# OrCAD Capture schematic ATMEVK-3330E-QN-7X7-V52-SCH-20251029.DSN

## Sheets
1 01. TITLE: title: ATM3330E EVALUATION BOARD; rev: 5.2; note: 052-50-611-xxxx
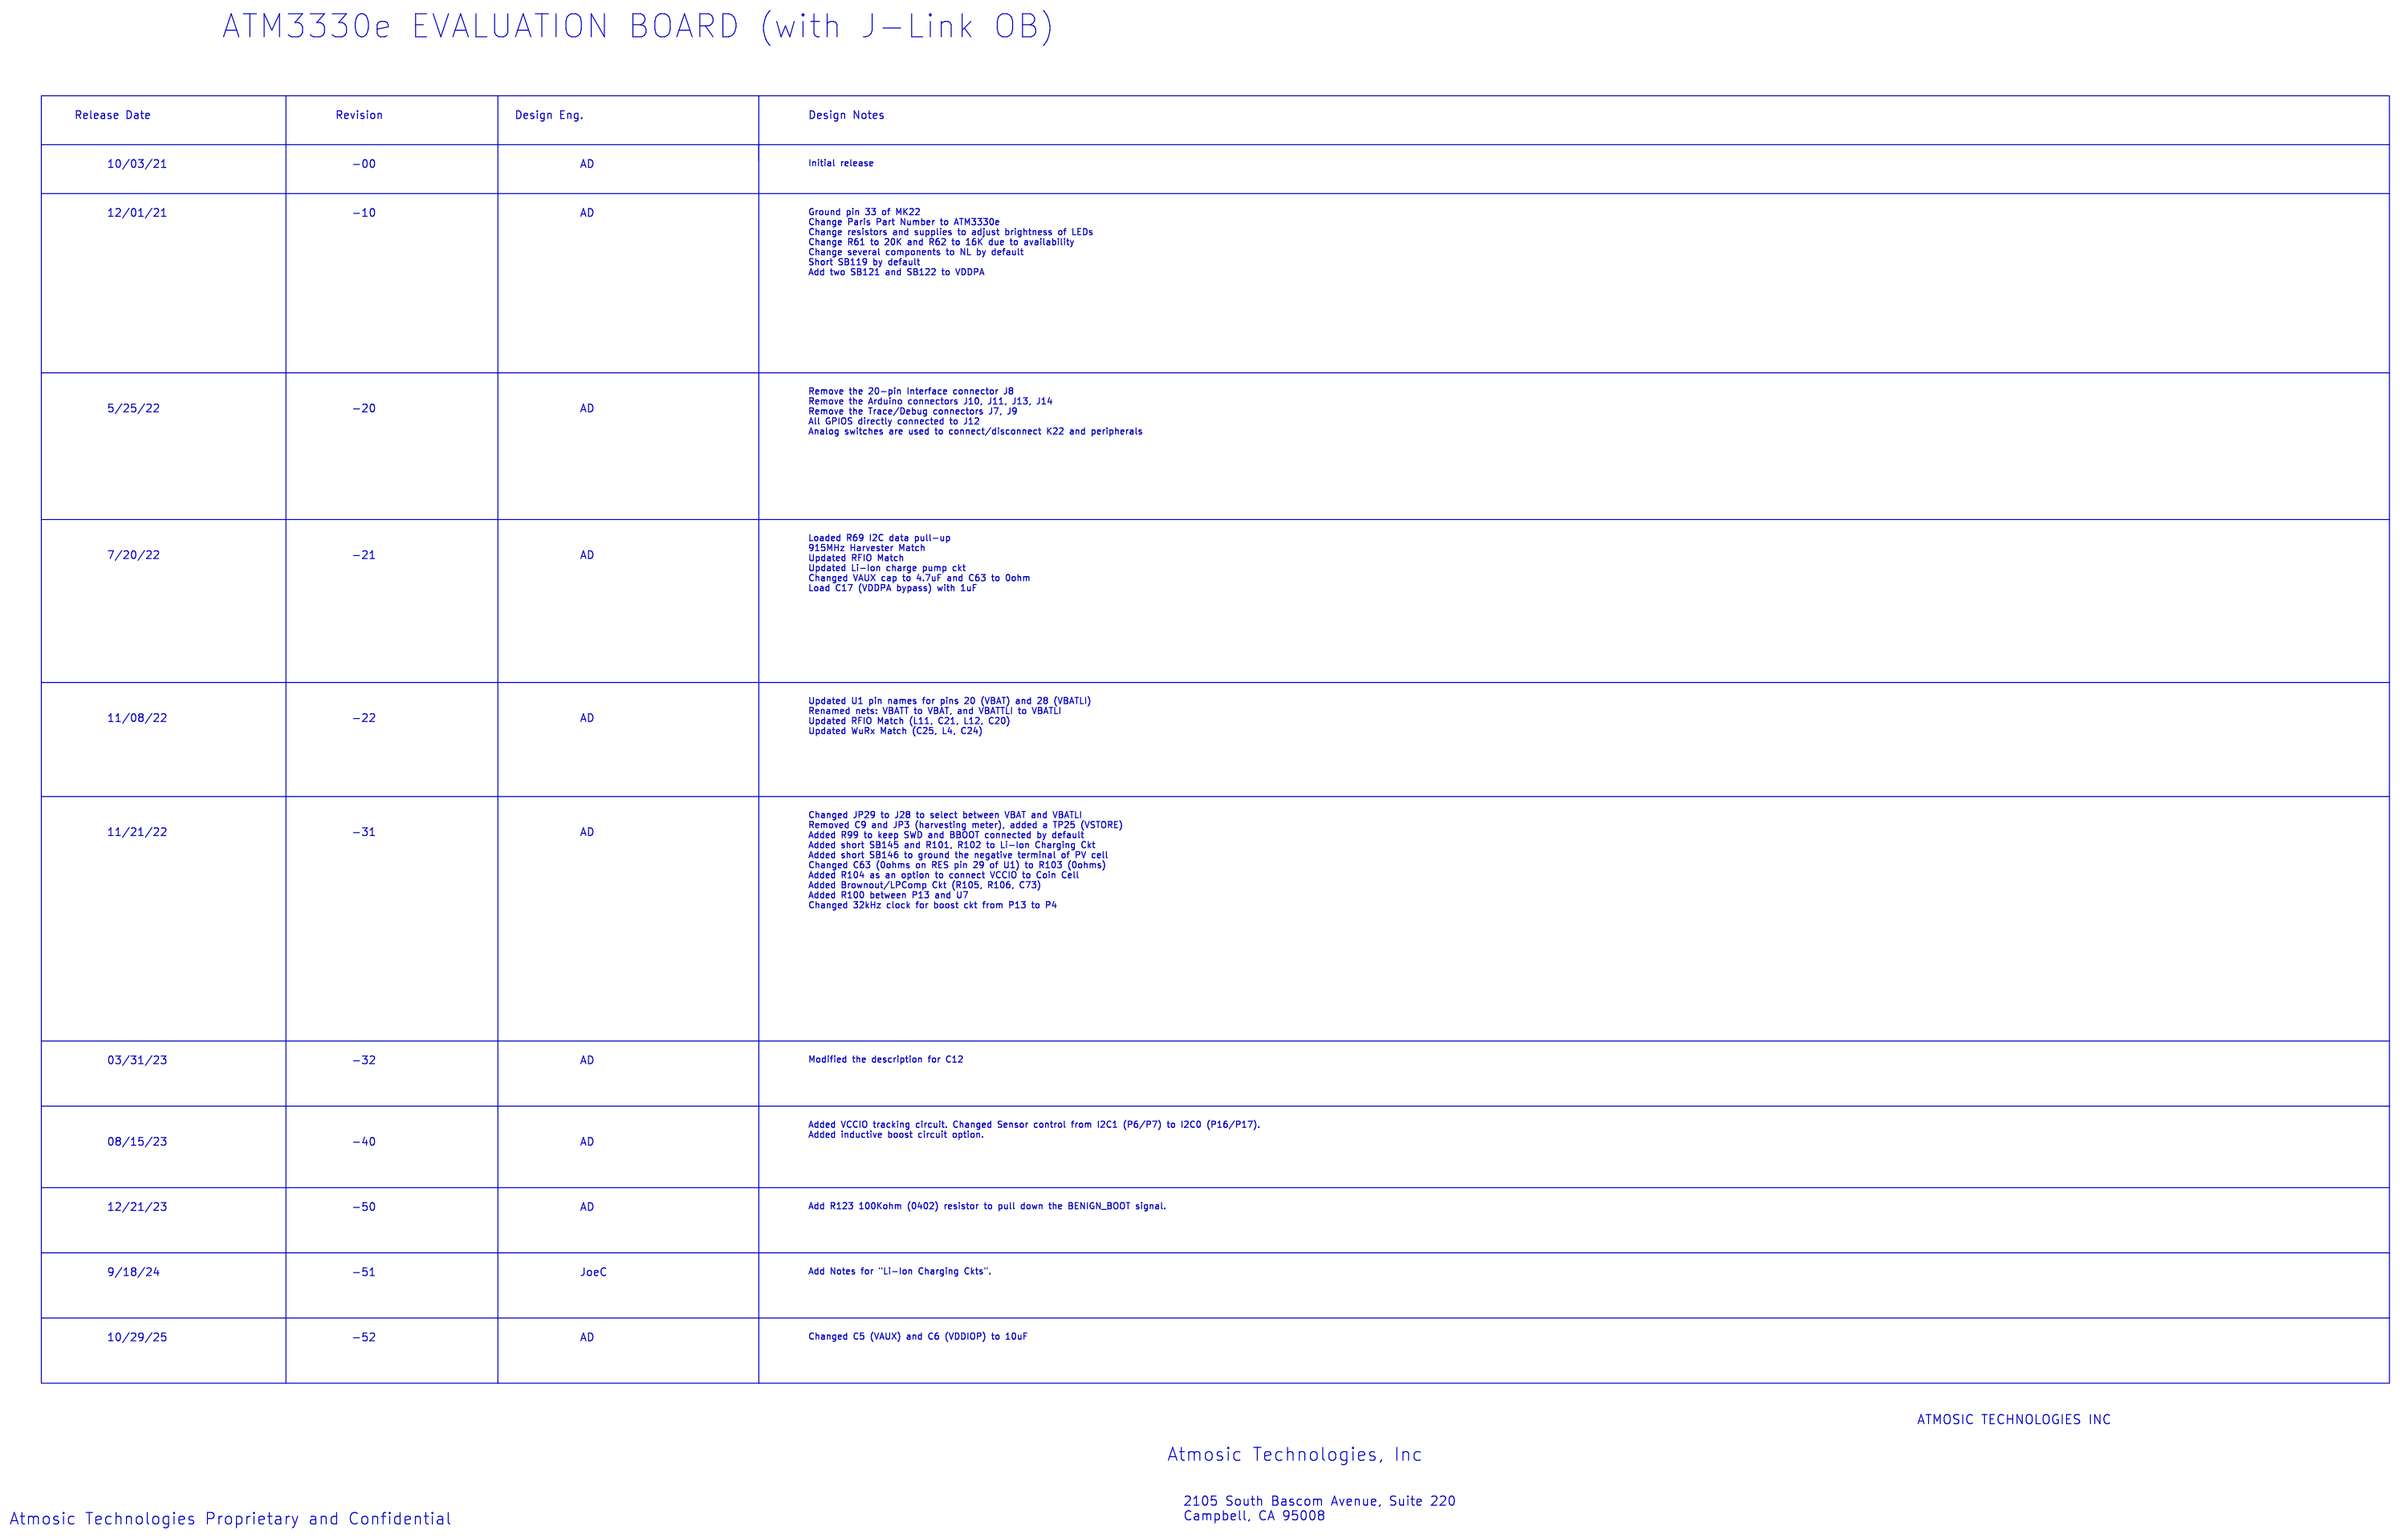
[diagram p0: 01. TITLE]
2 02. Block Diagram
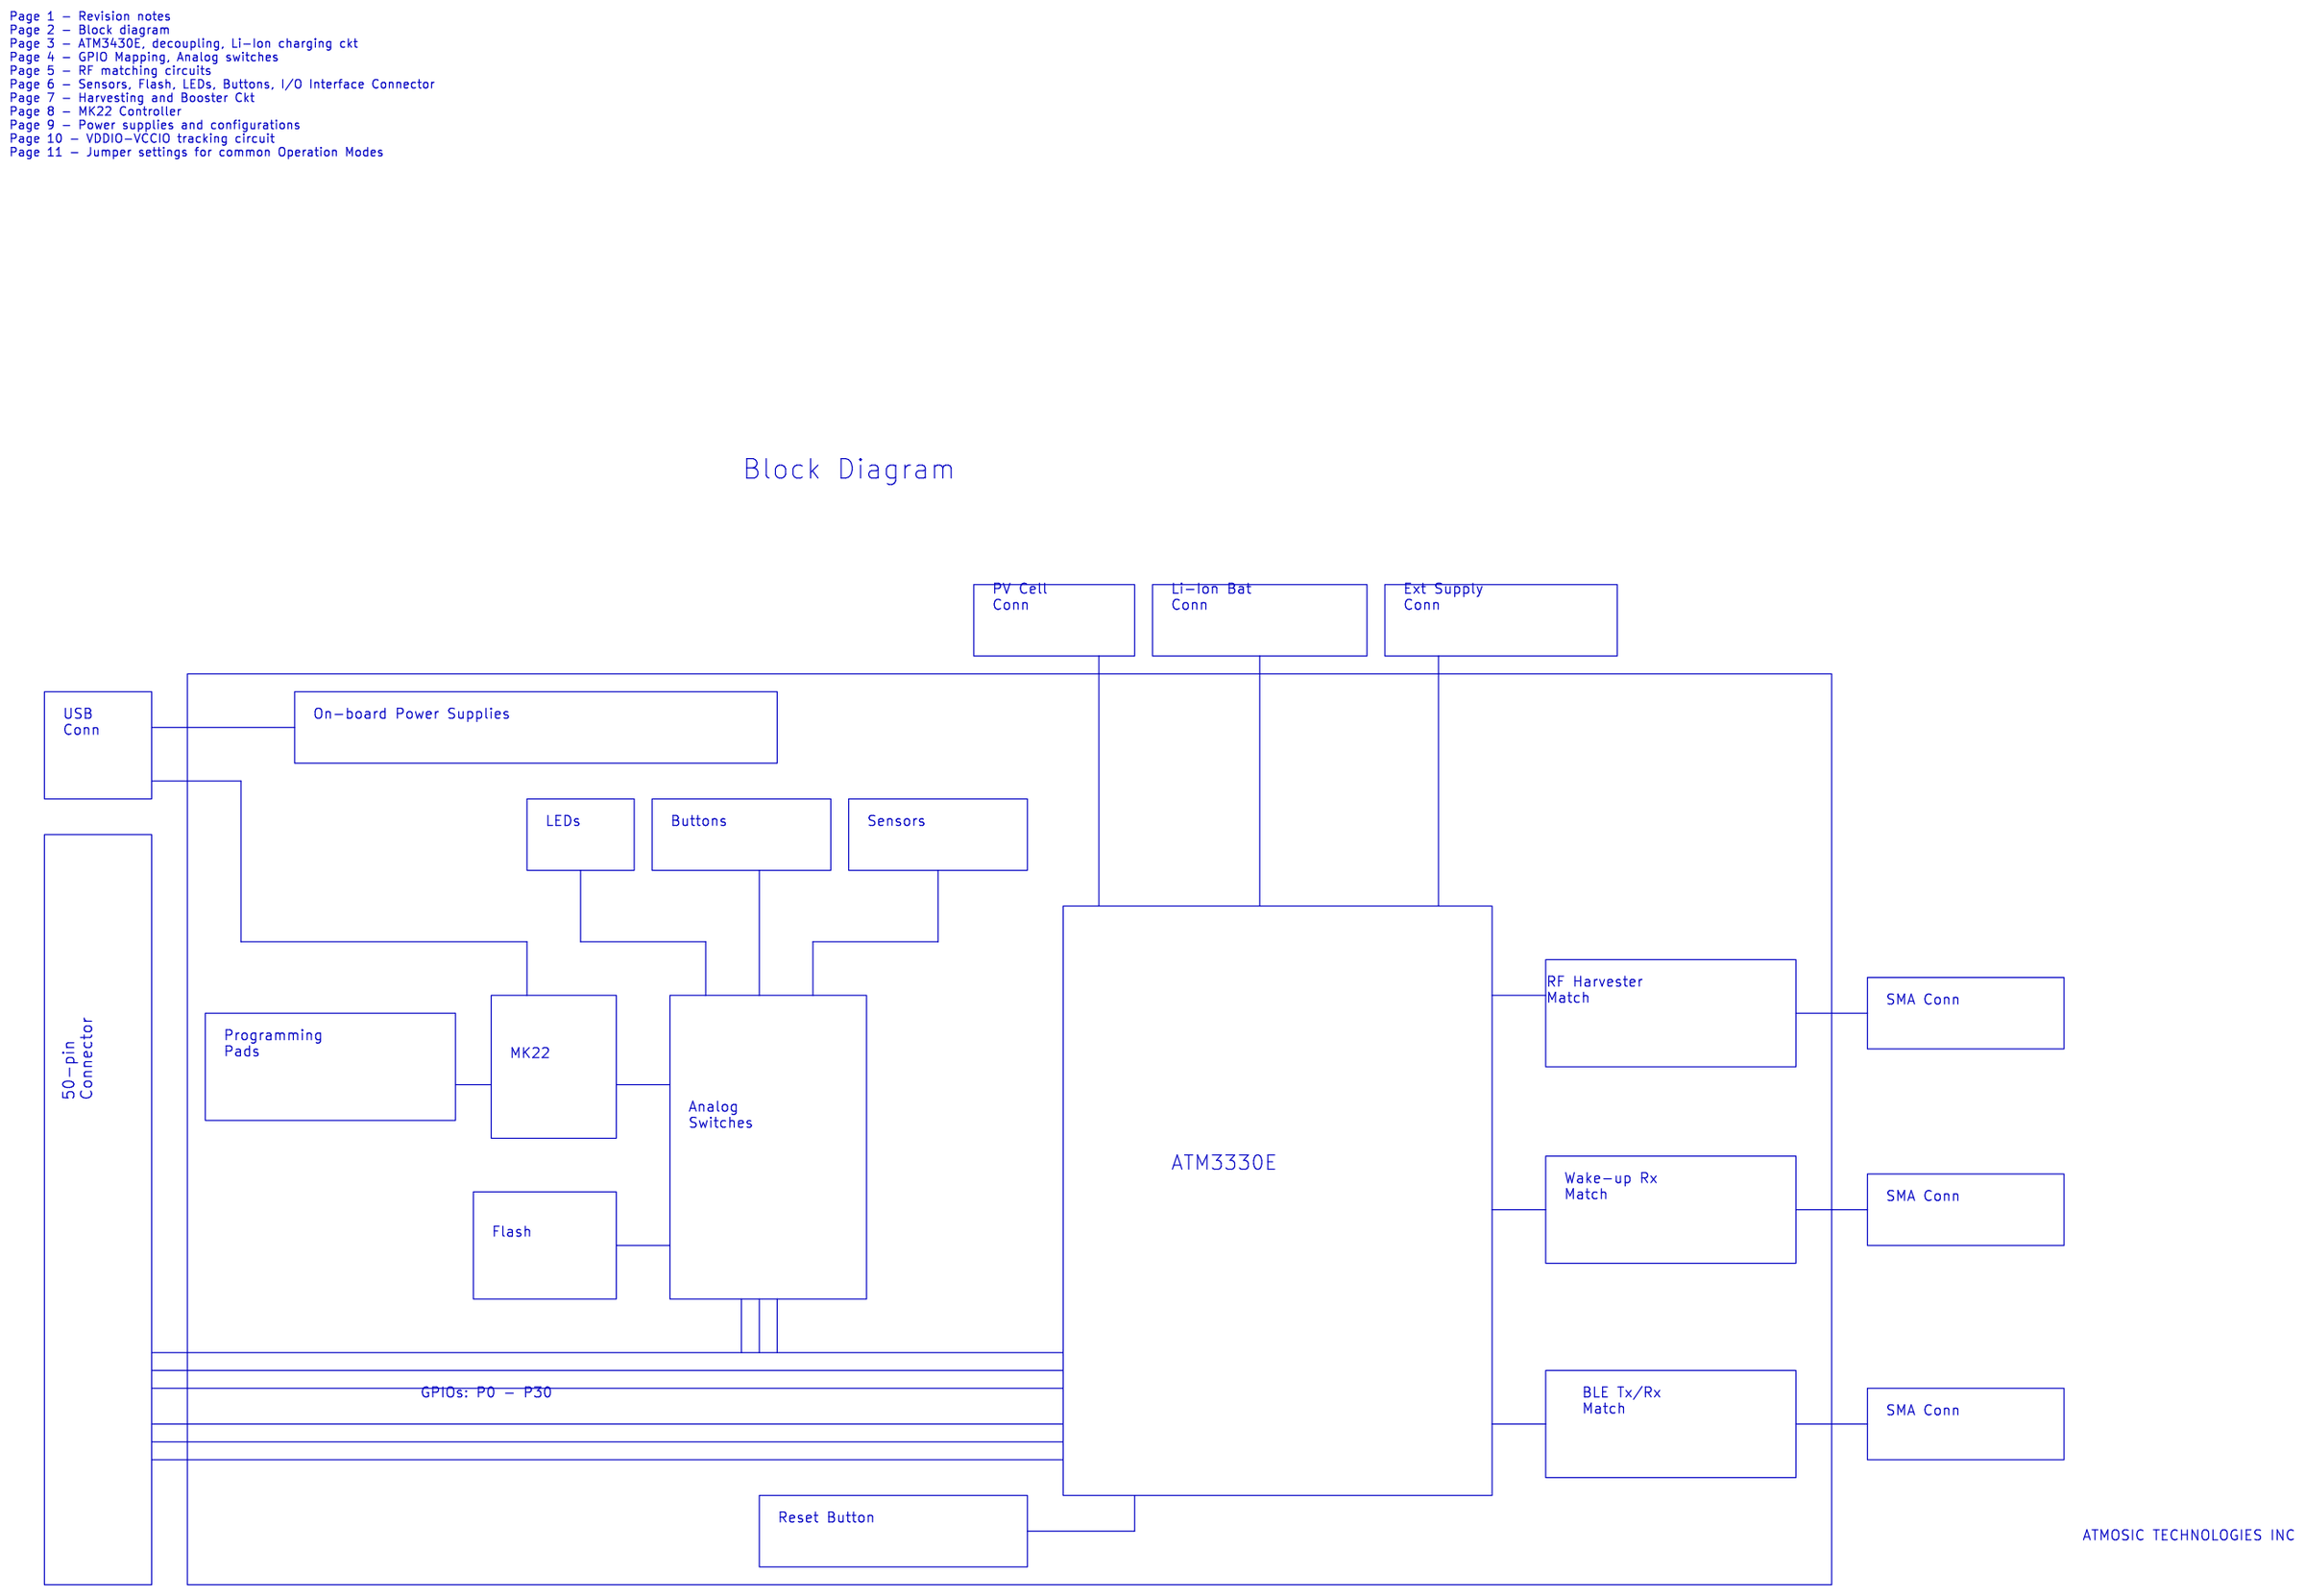
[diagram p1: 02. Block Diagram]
3 03. ATM3330E: size B
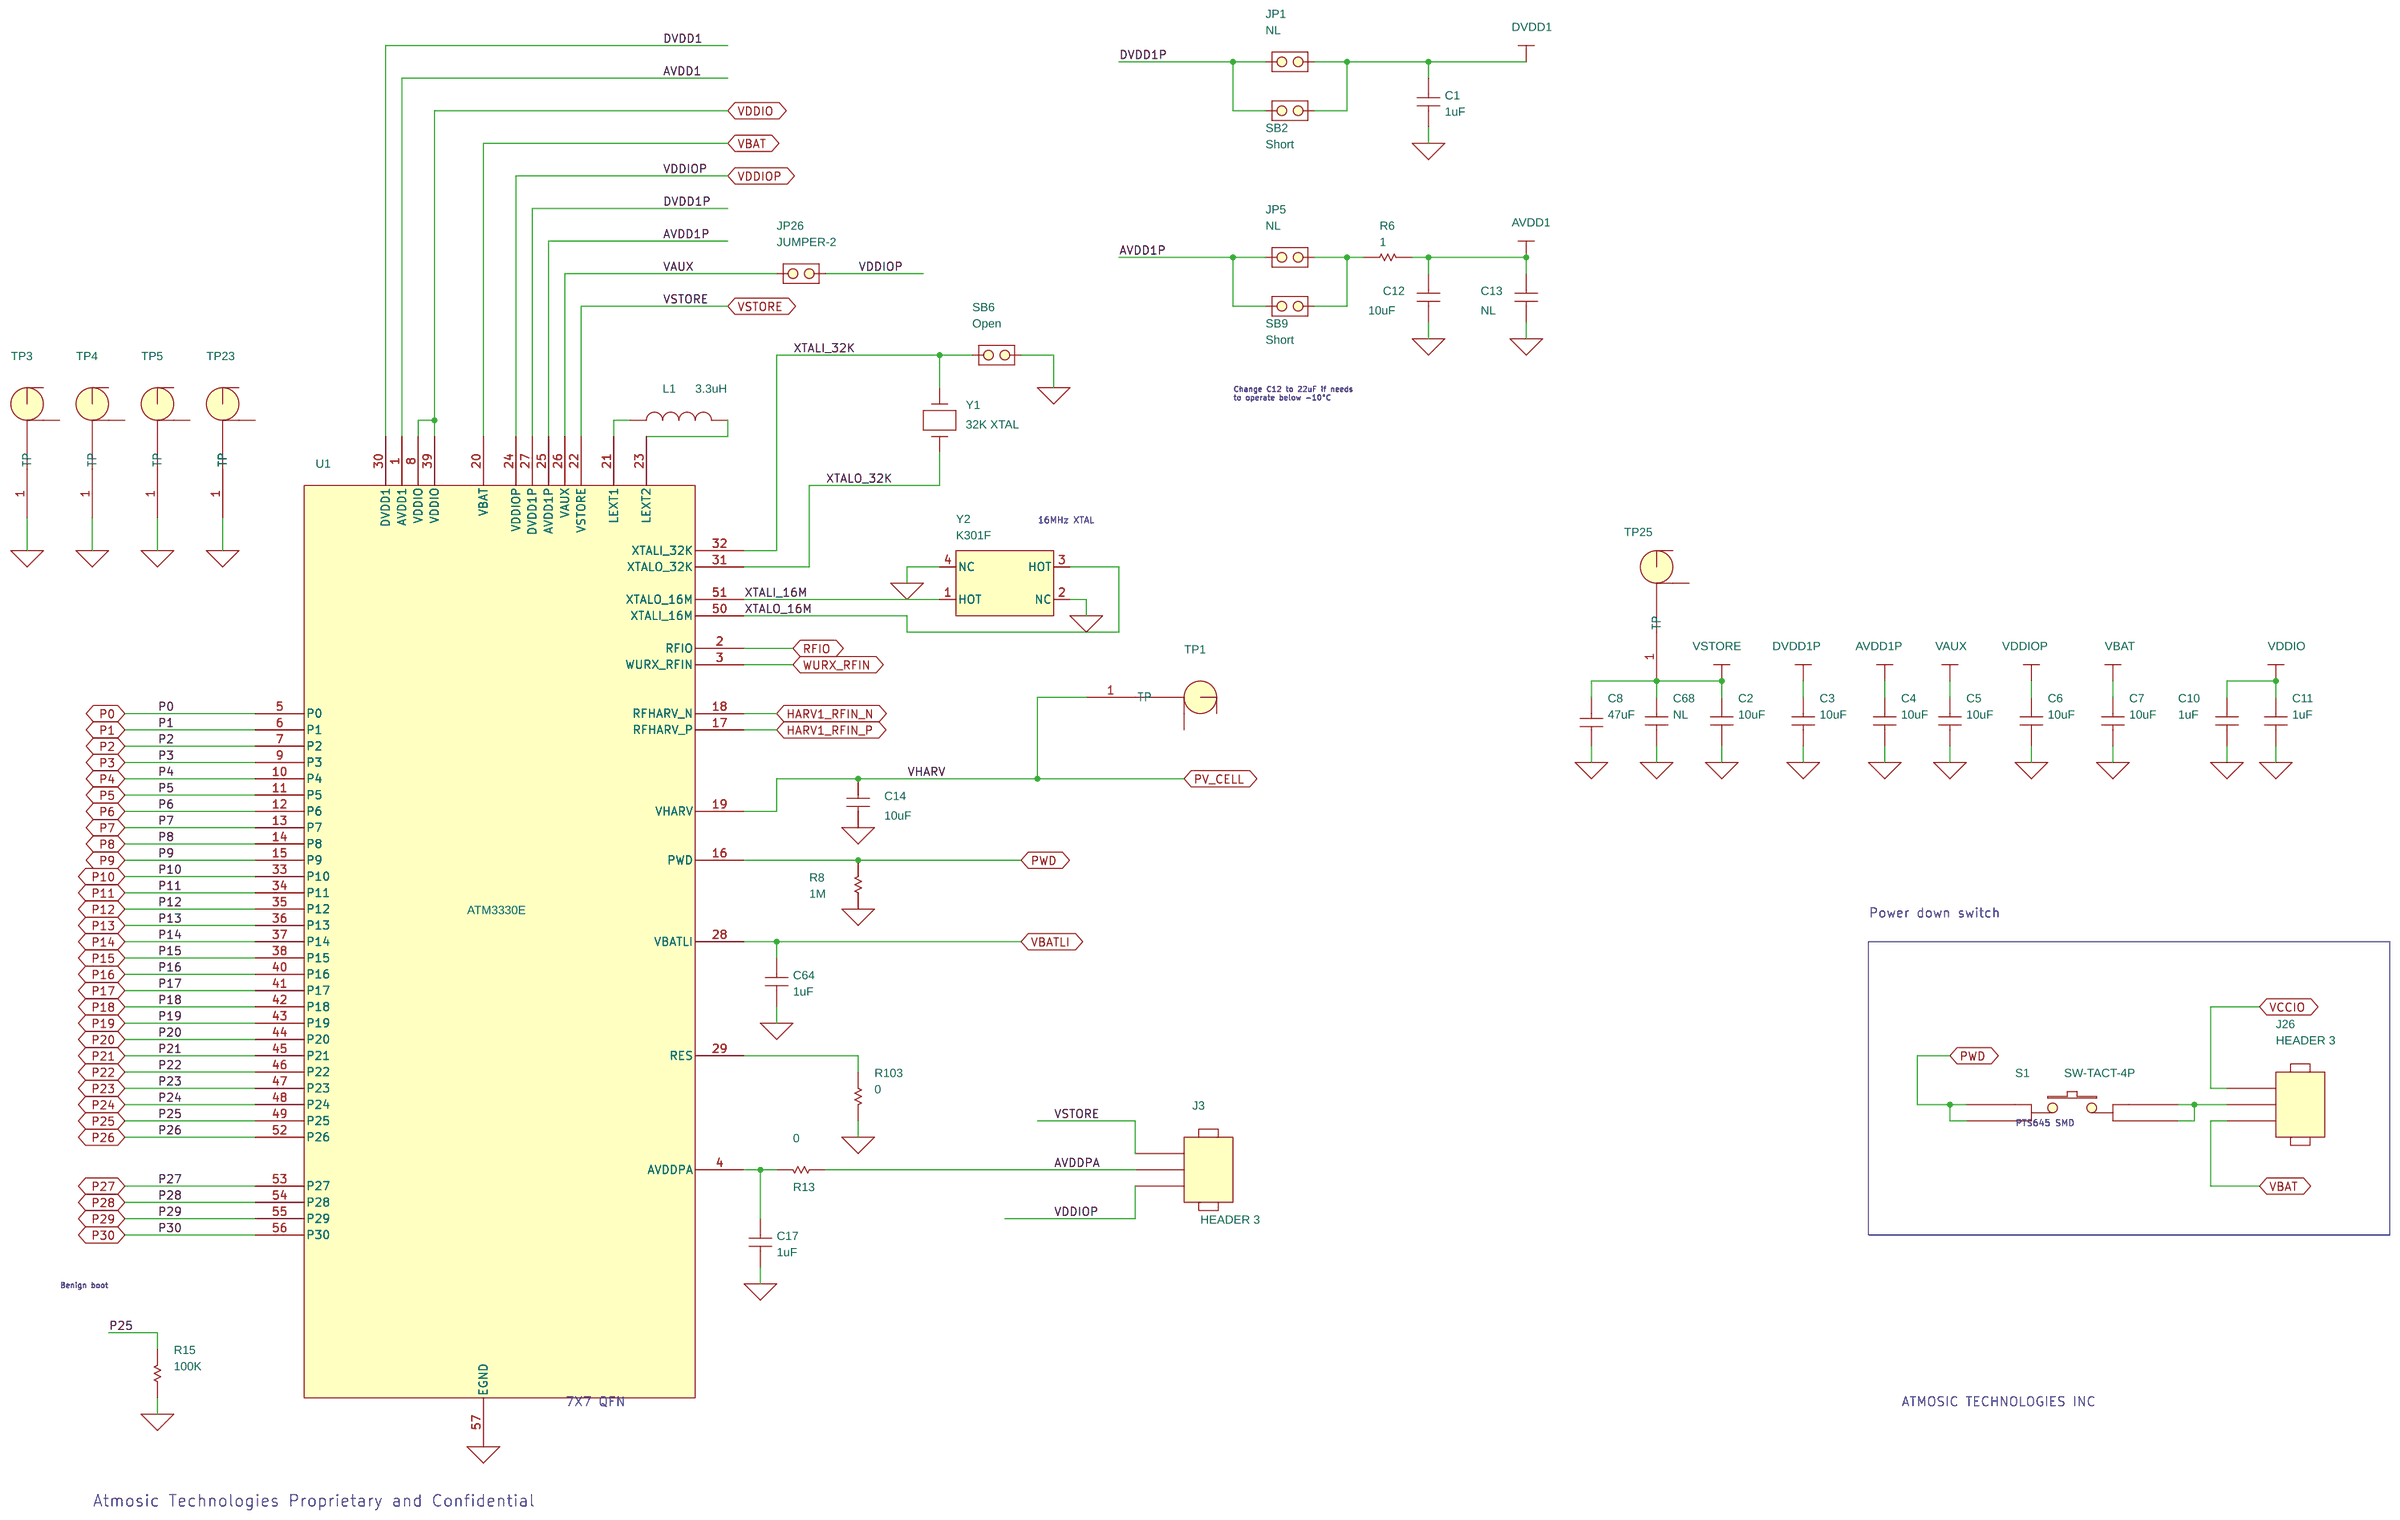
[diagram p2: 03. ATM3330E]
4 04. GPIO Mapping: size B
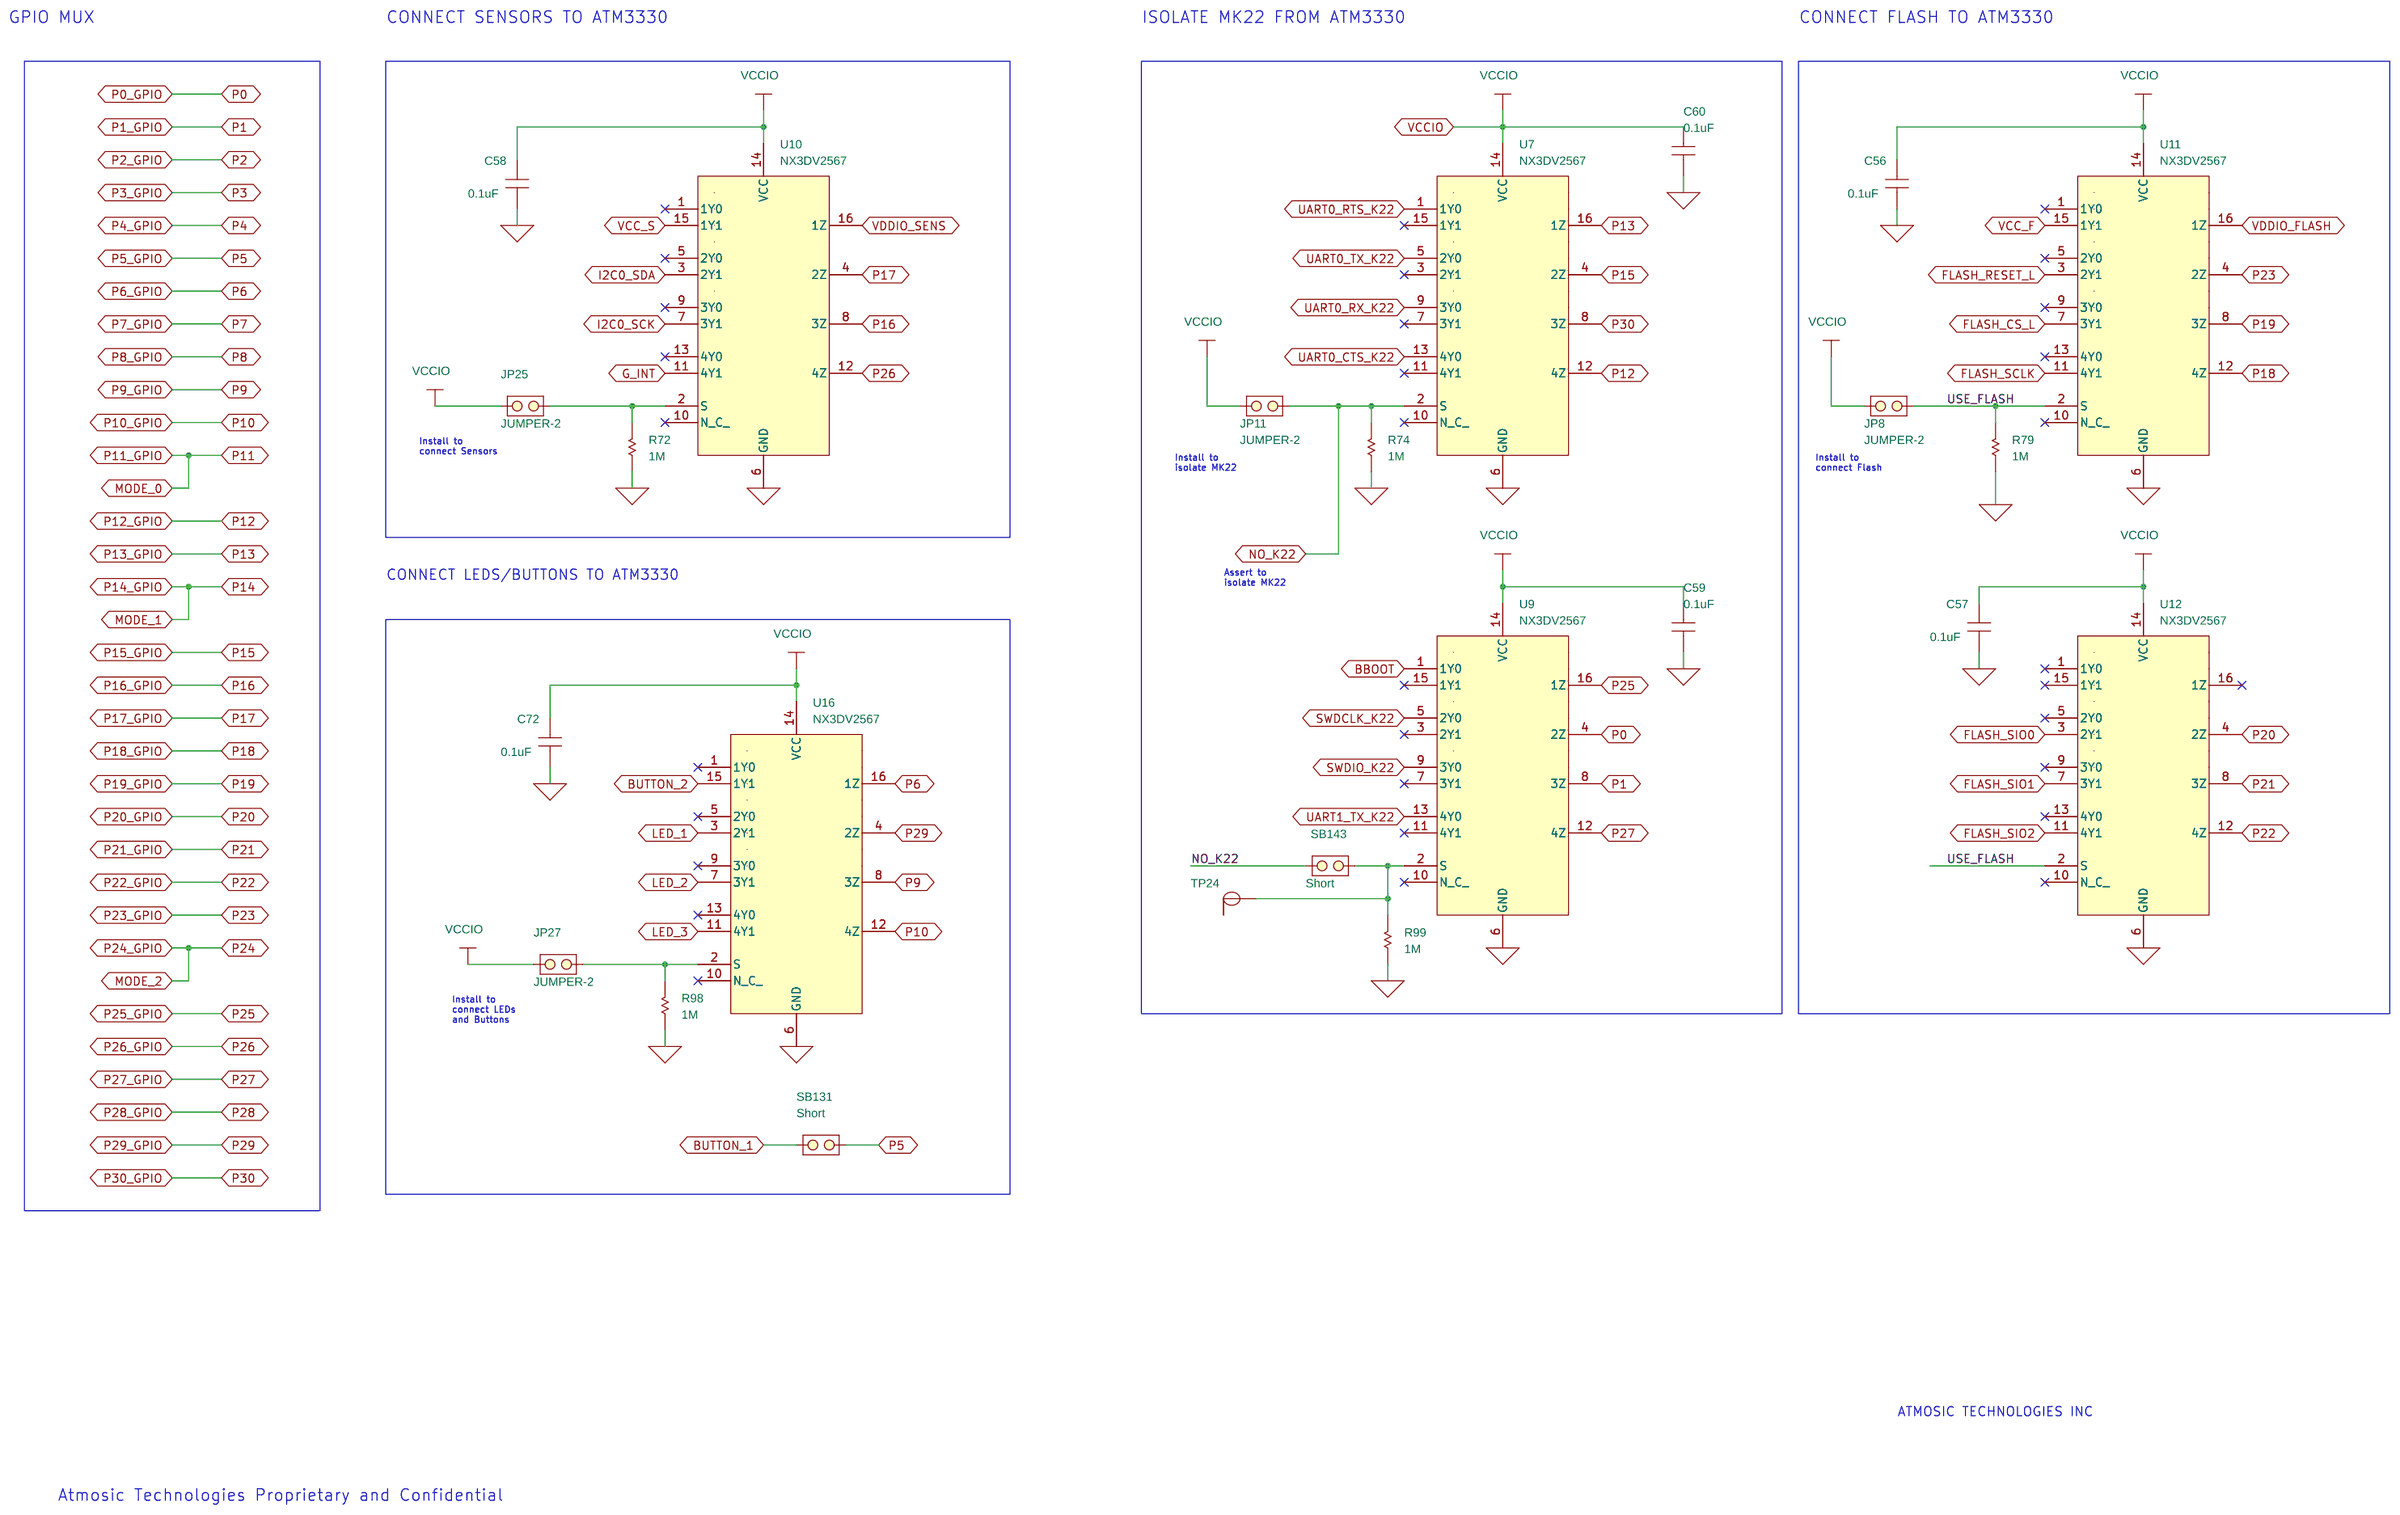
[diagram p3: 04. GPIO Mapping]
5 07. Harvesting: size B
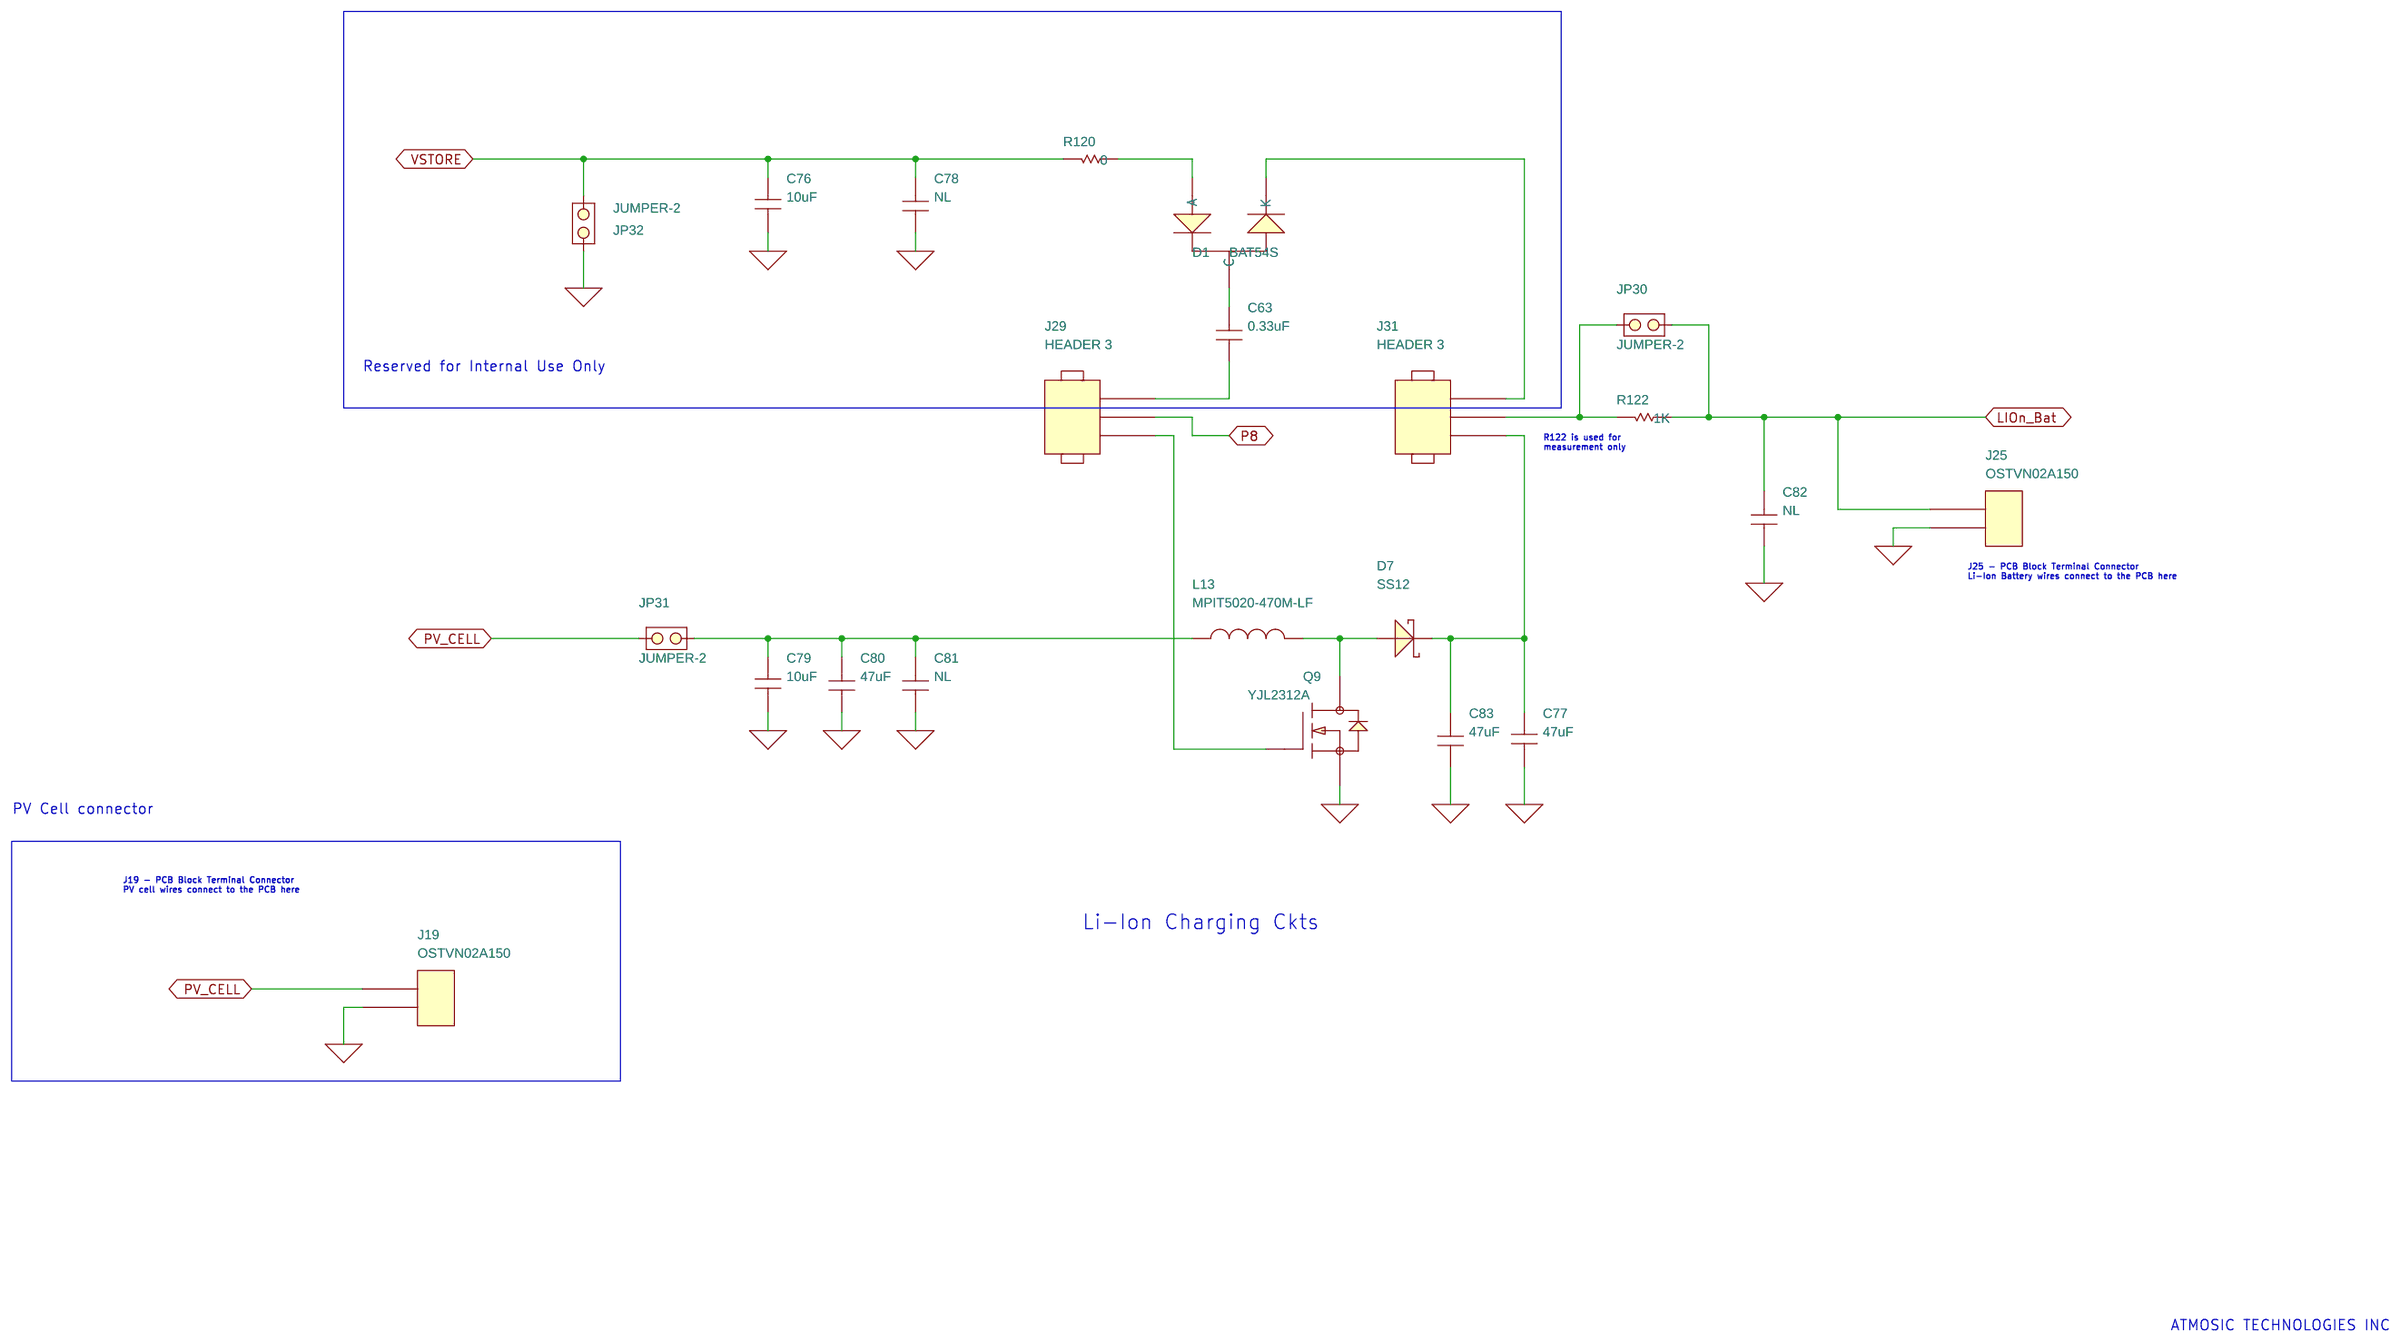
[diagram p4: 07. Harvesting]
6 08. MK22: size B
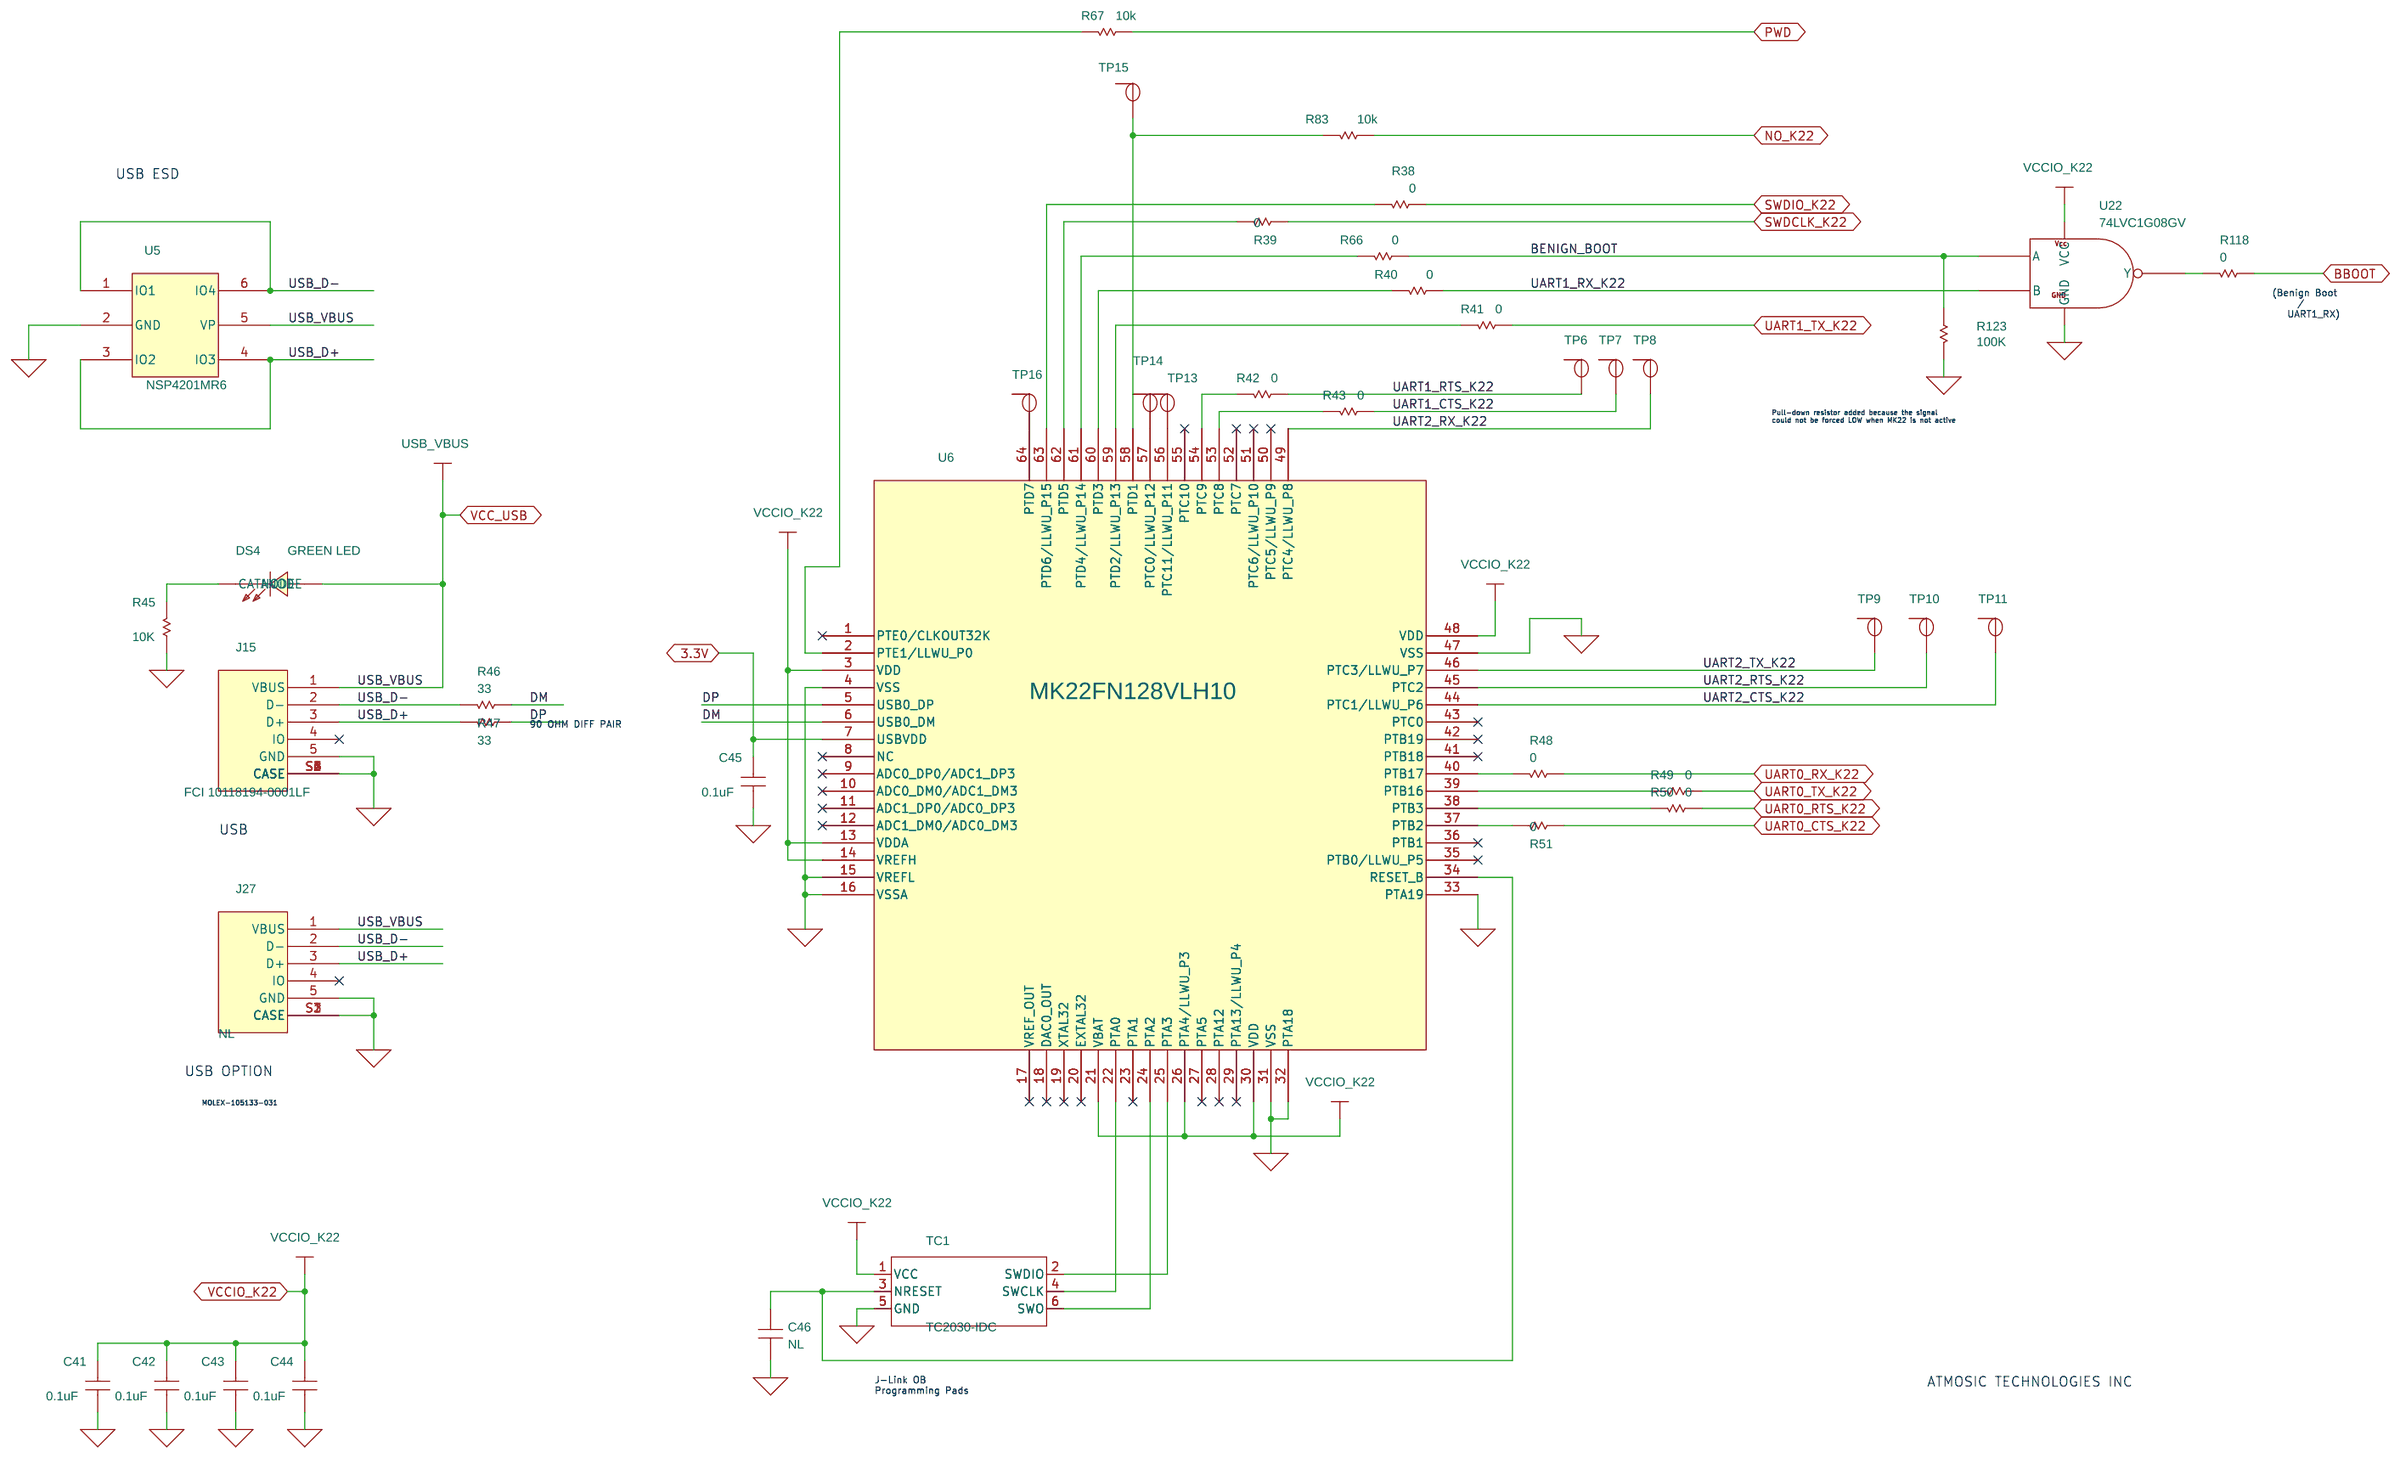
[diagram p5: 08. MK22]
7 09. Power: size B
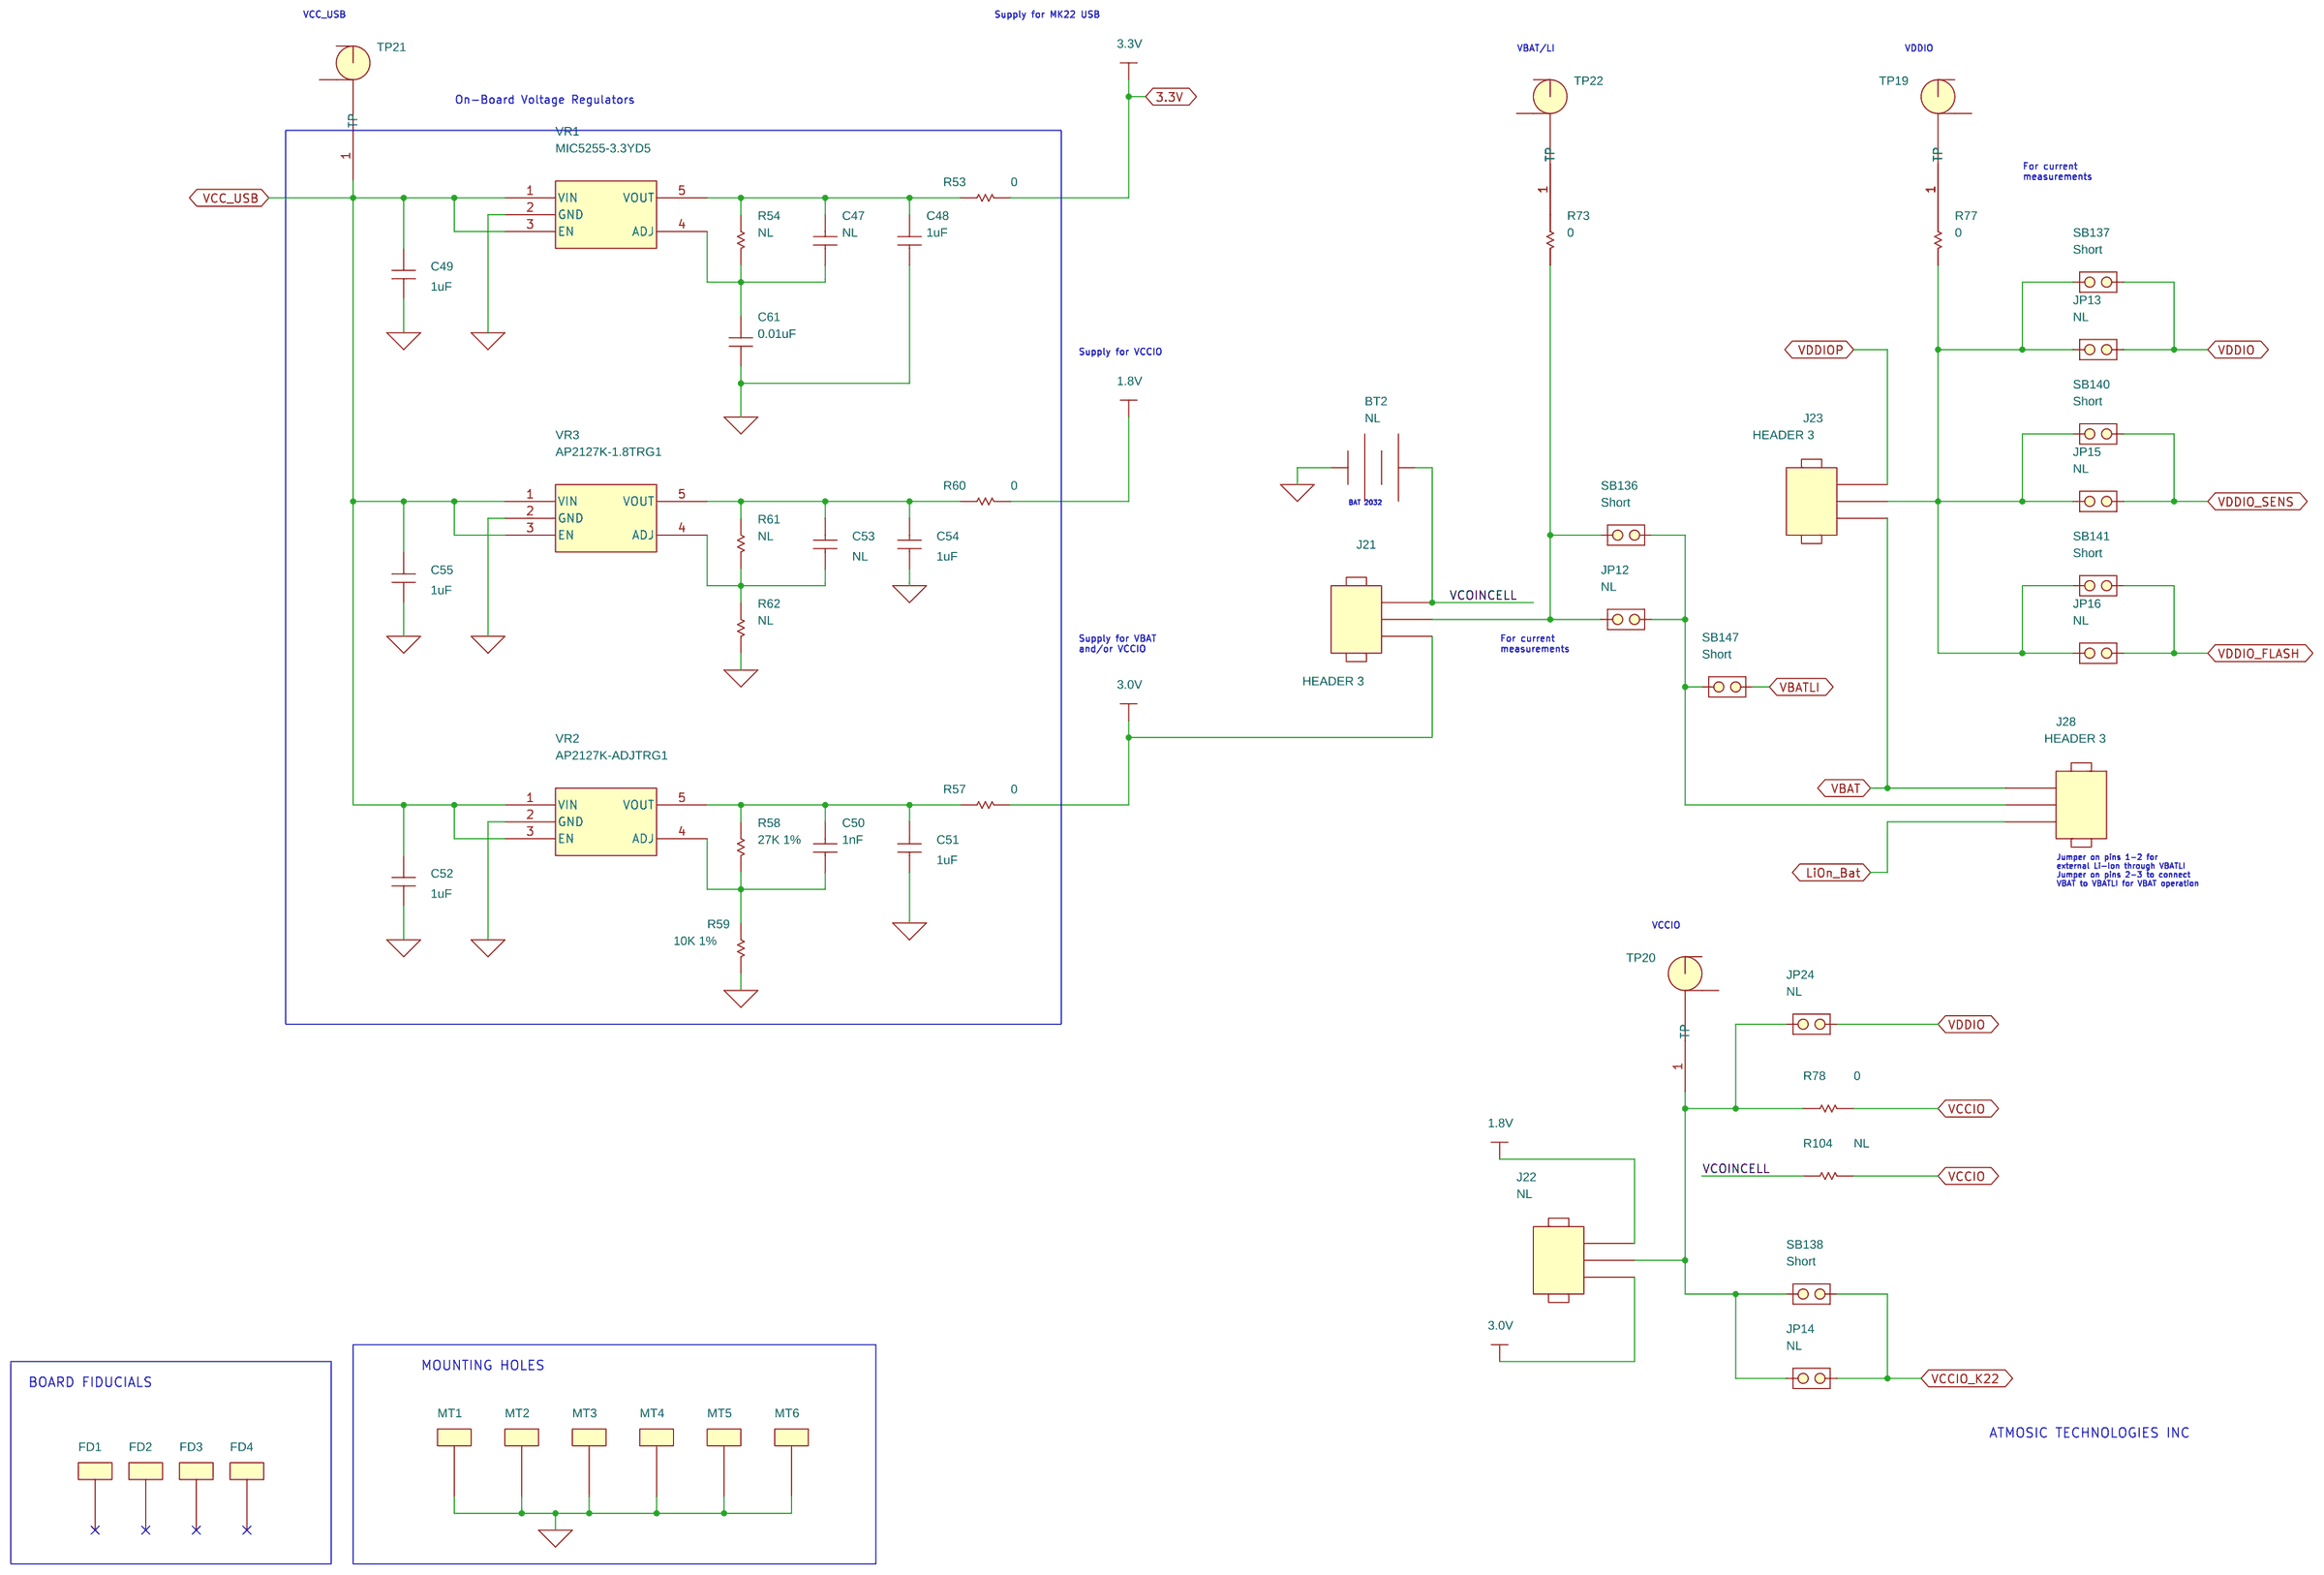
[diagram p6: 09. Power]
8 10. VDDIO-VCCIO Tracking: size B
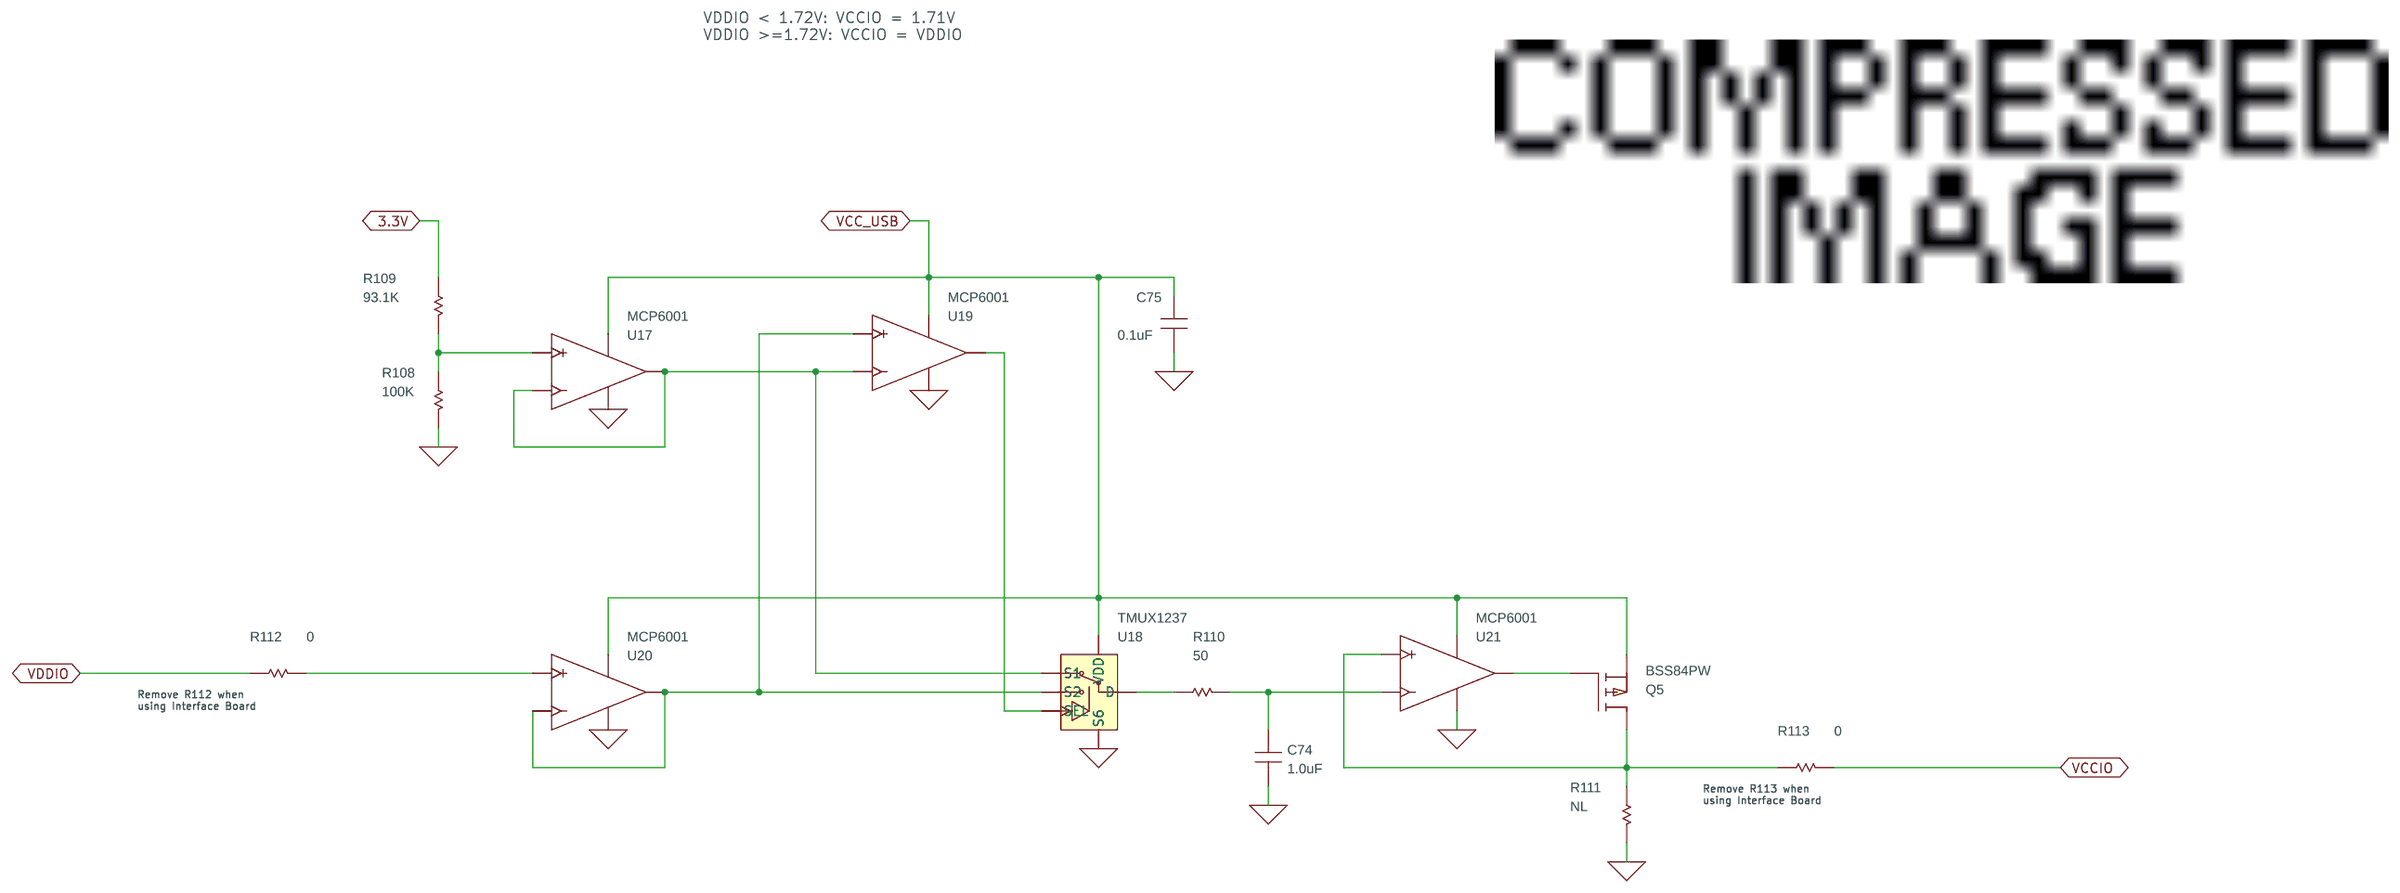
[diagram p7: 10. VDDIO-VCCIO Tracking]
9 11. Power Configuration
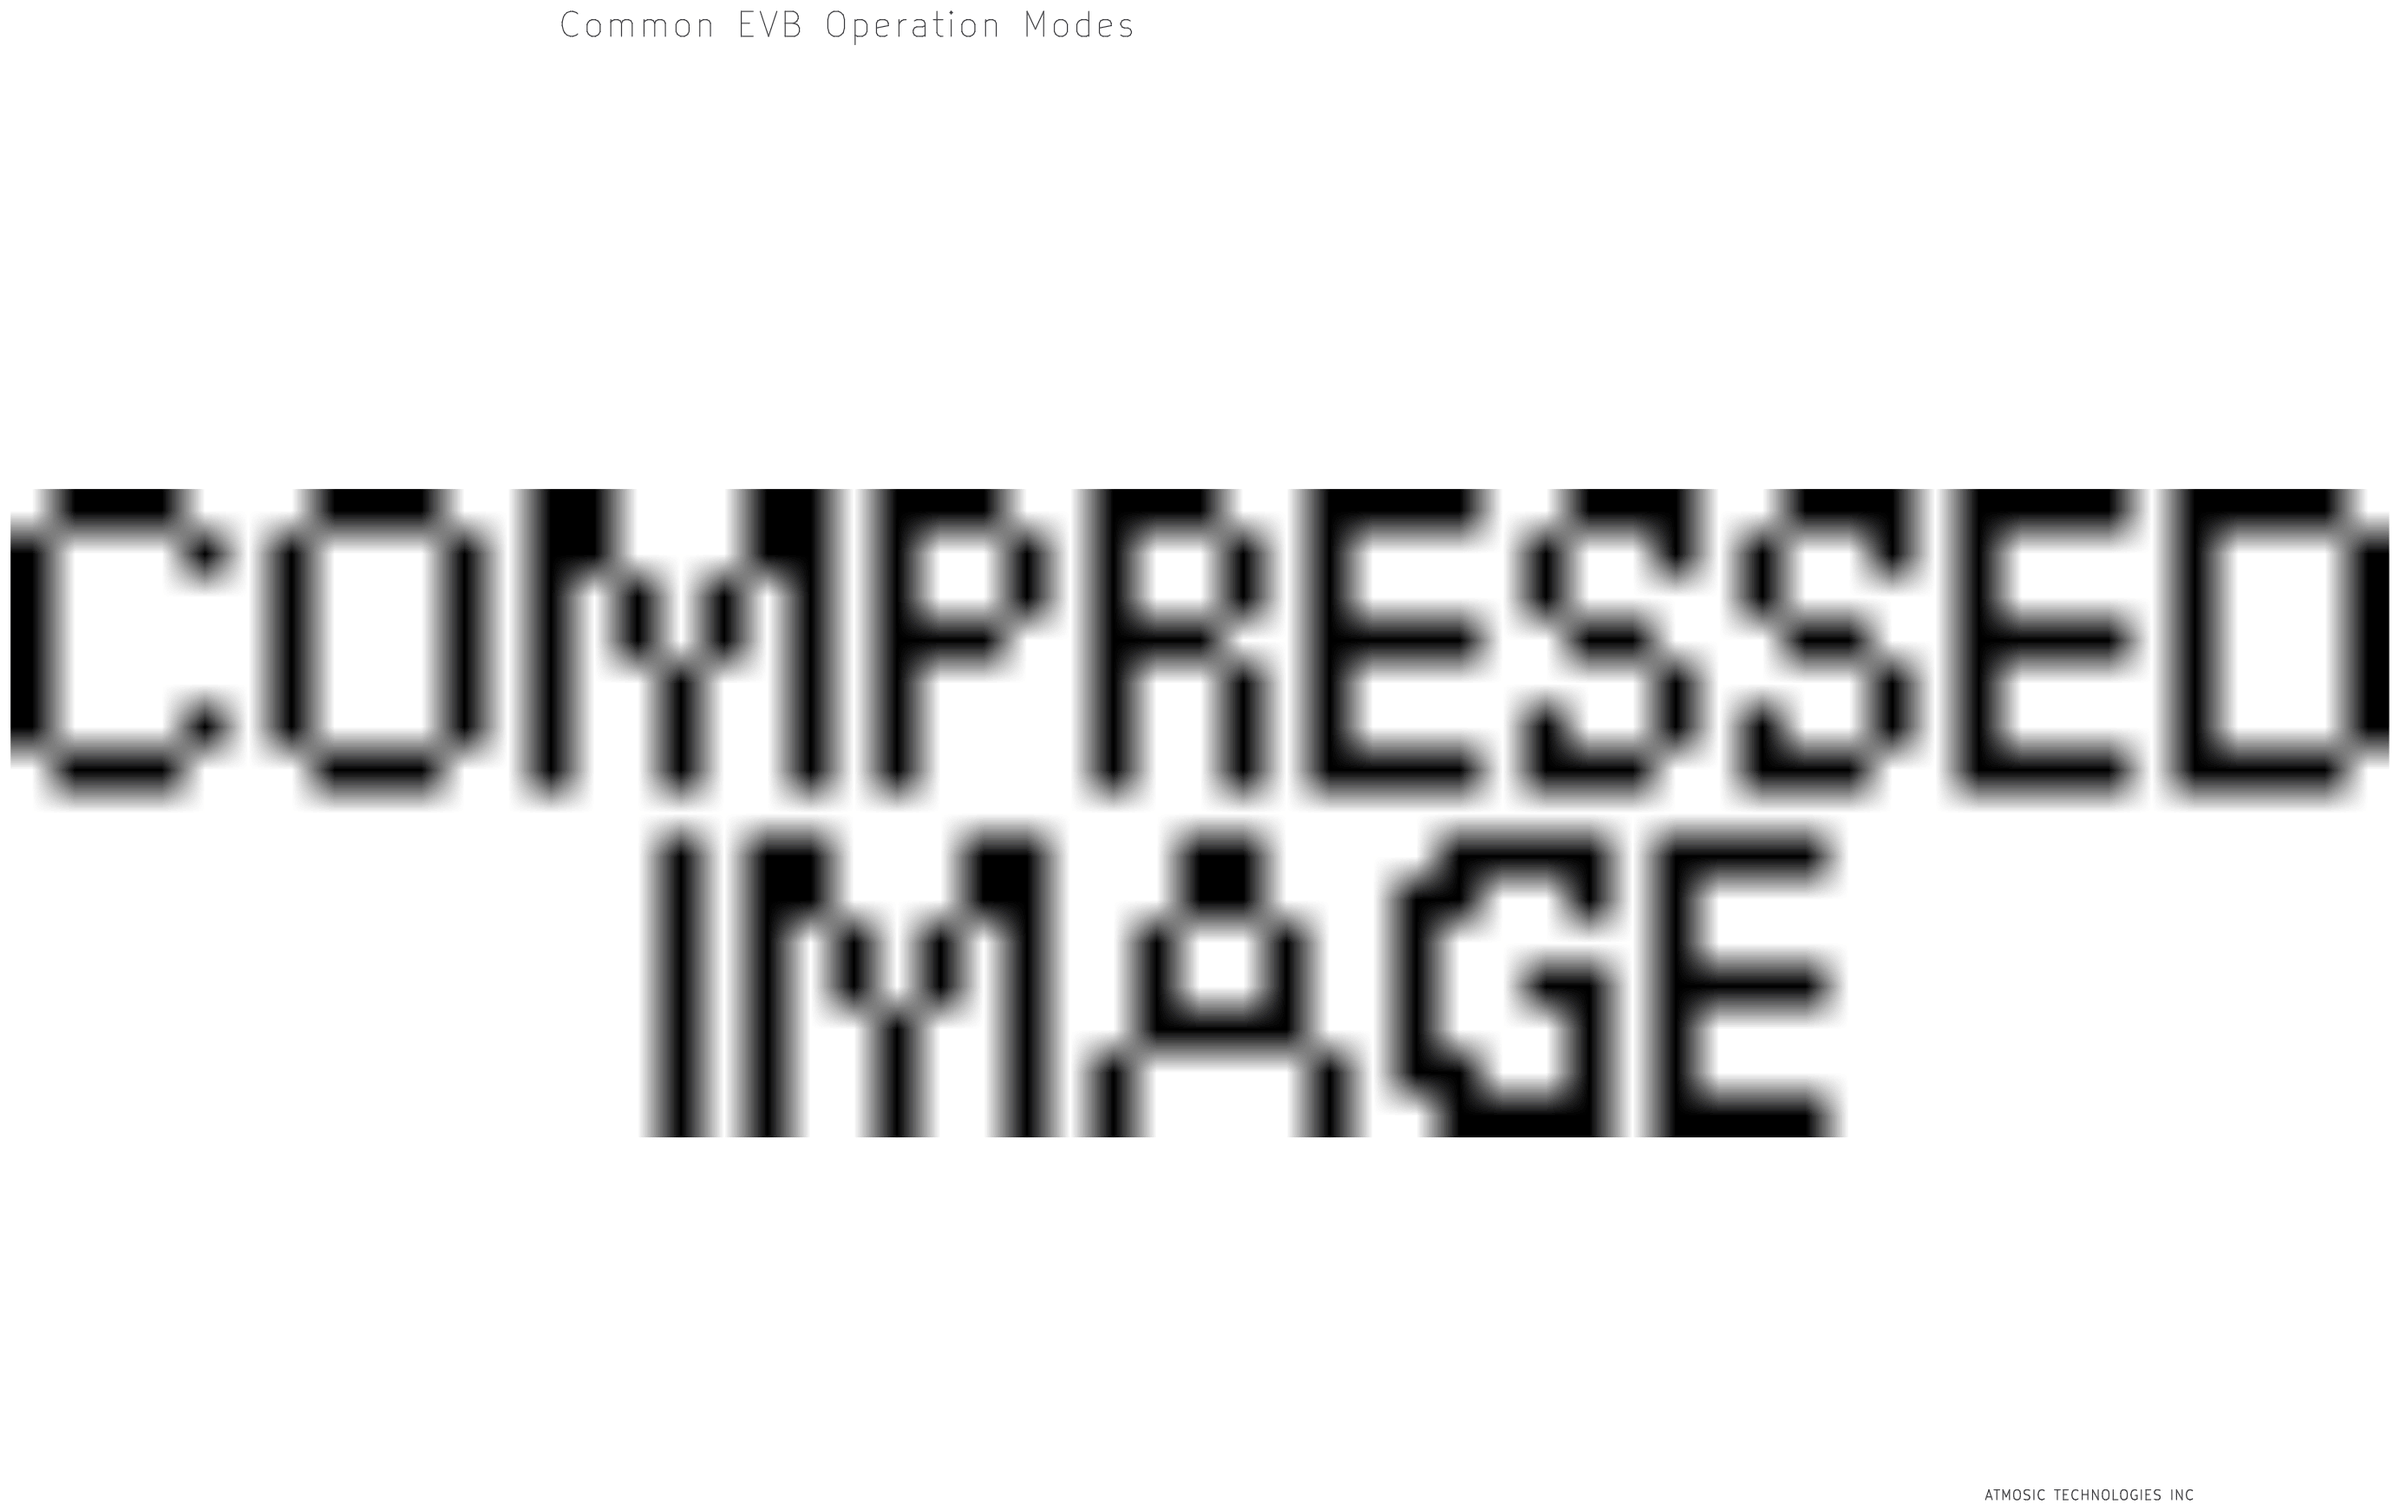
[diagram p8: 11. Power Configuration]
10 05. RF (RFIO/WuRX/HARV): size B
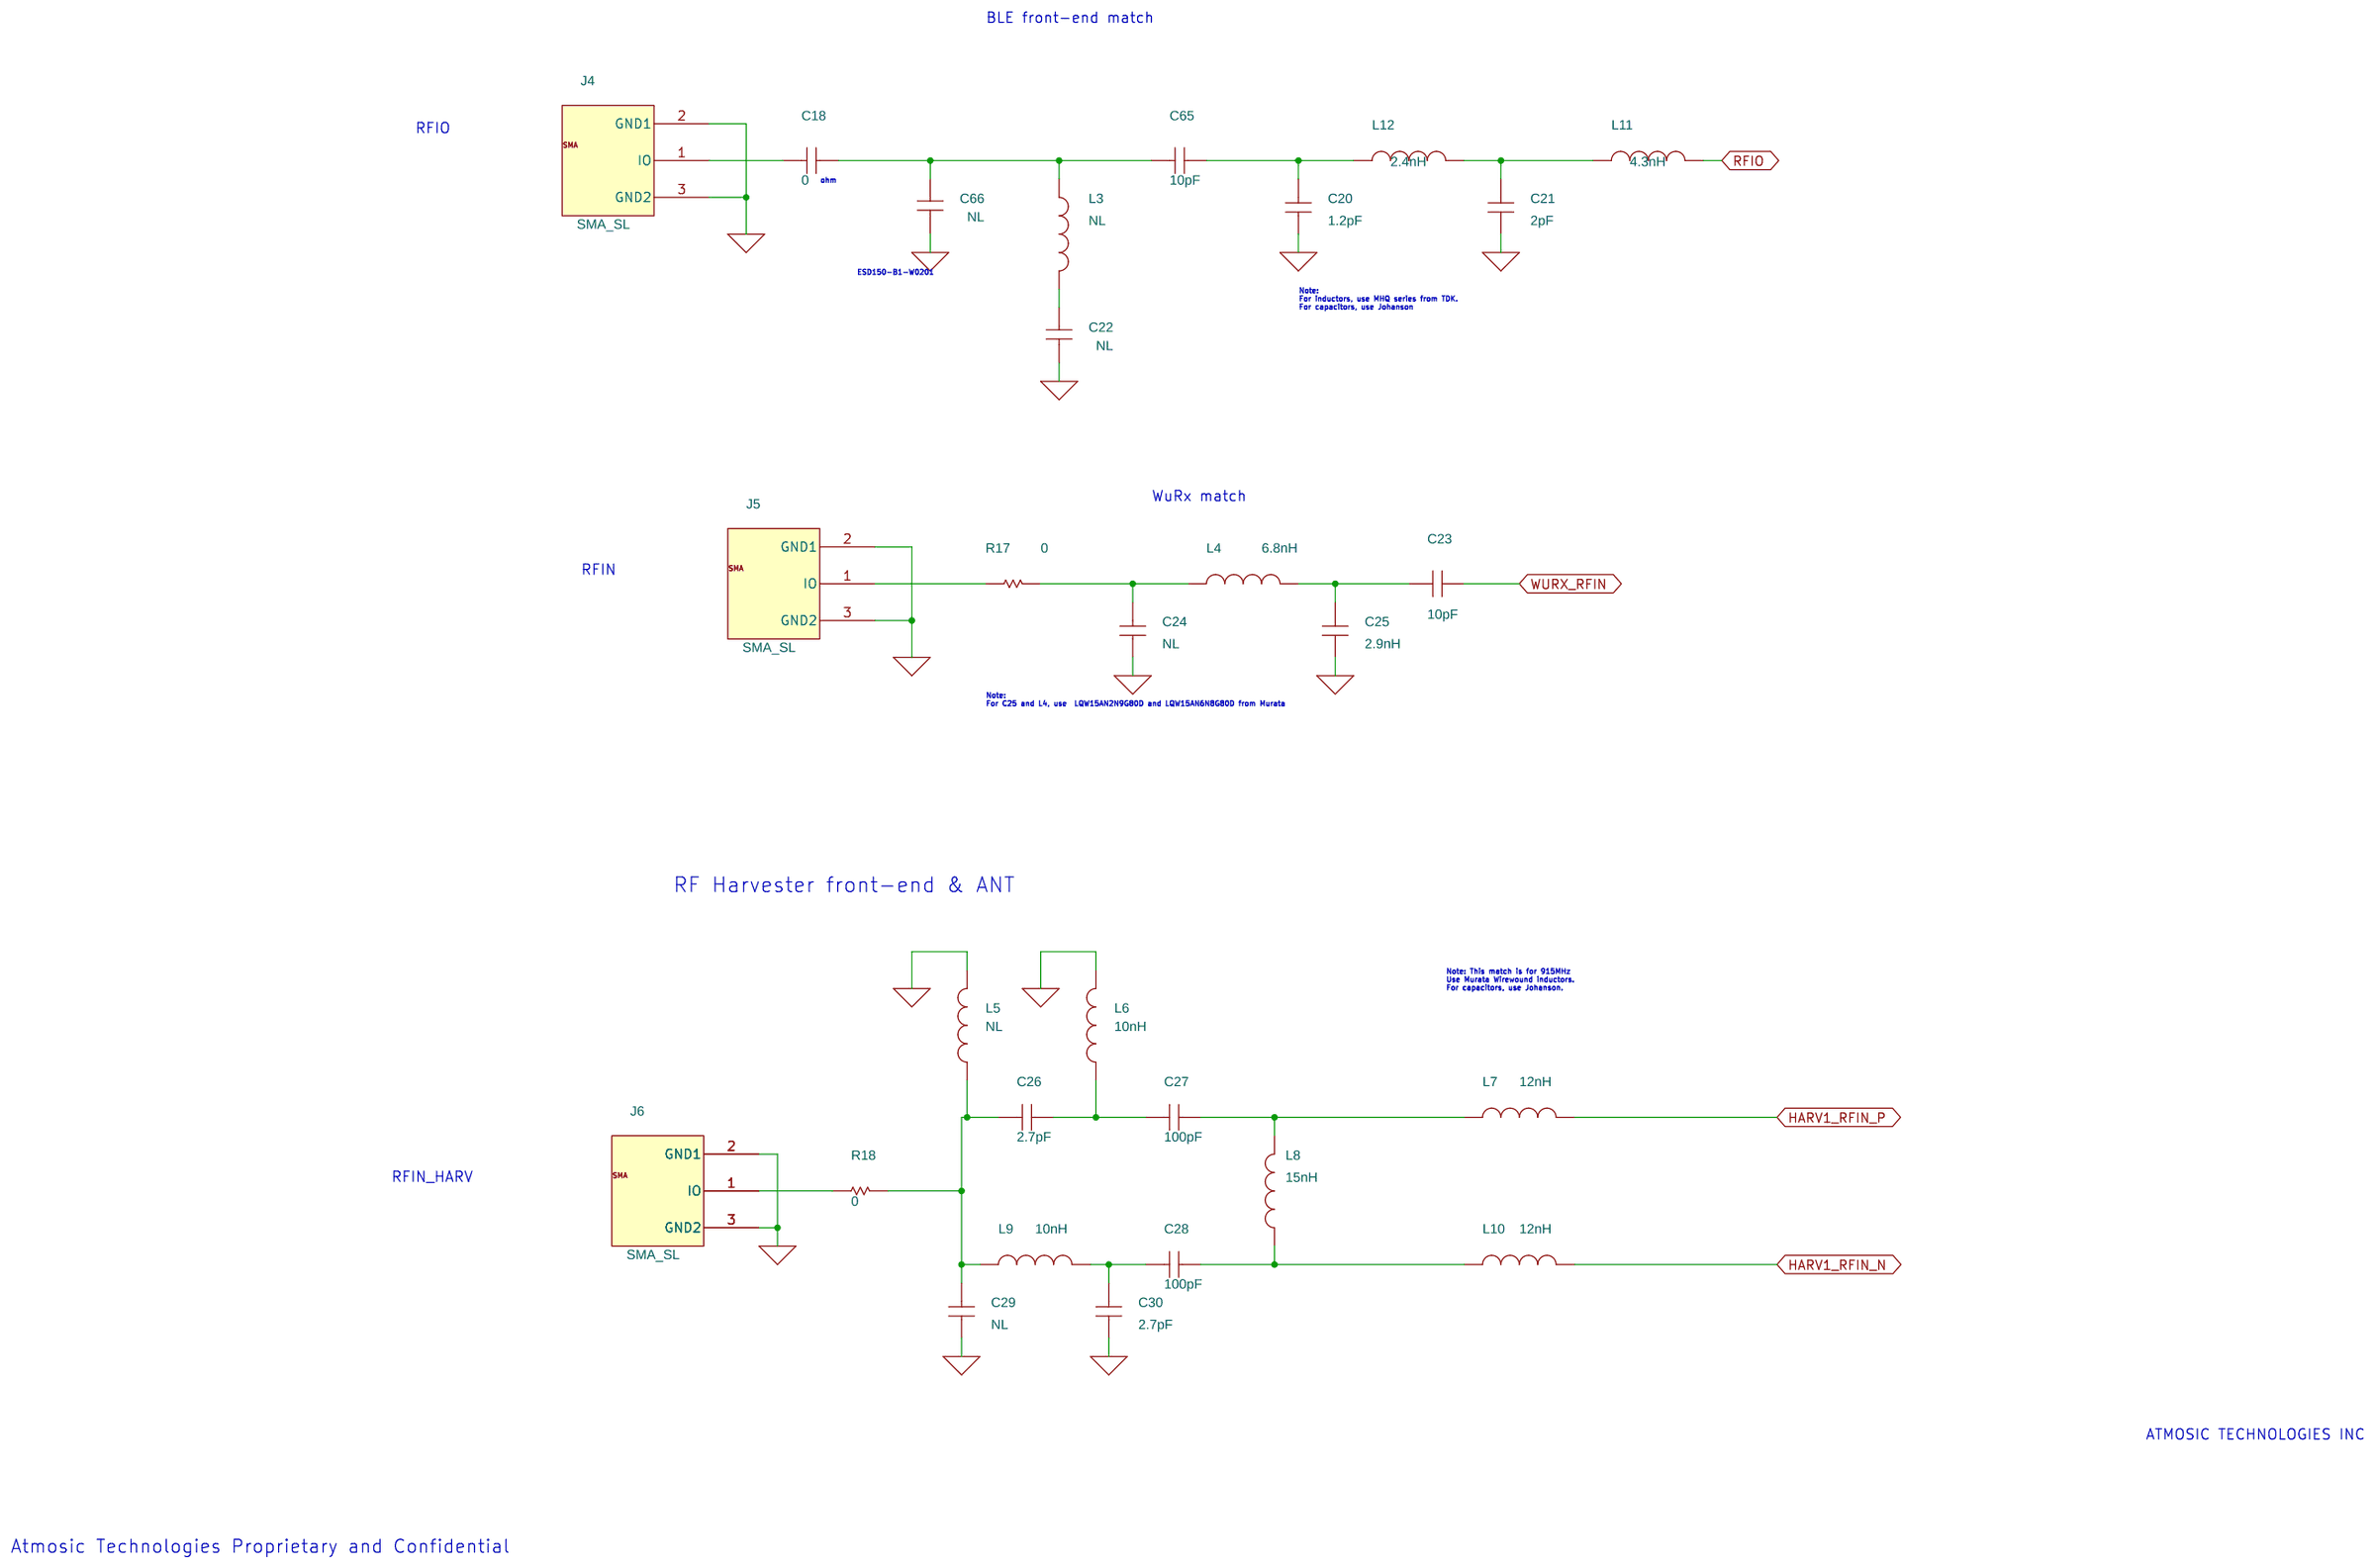
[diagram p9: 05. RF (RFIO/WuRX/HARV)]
11 06. Buttons LEDs Sensors I/O: size B
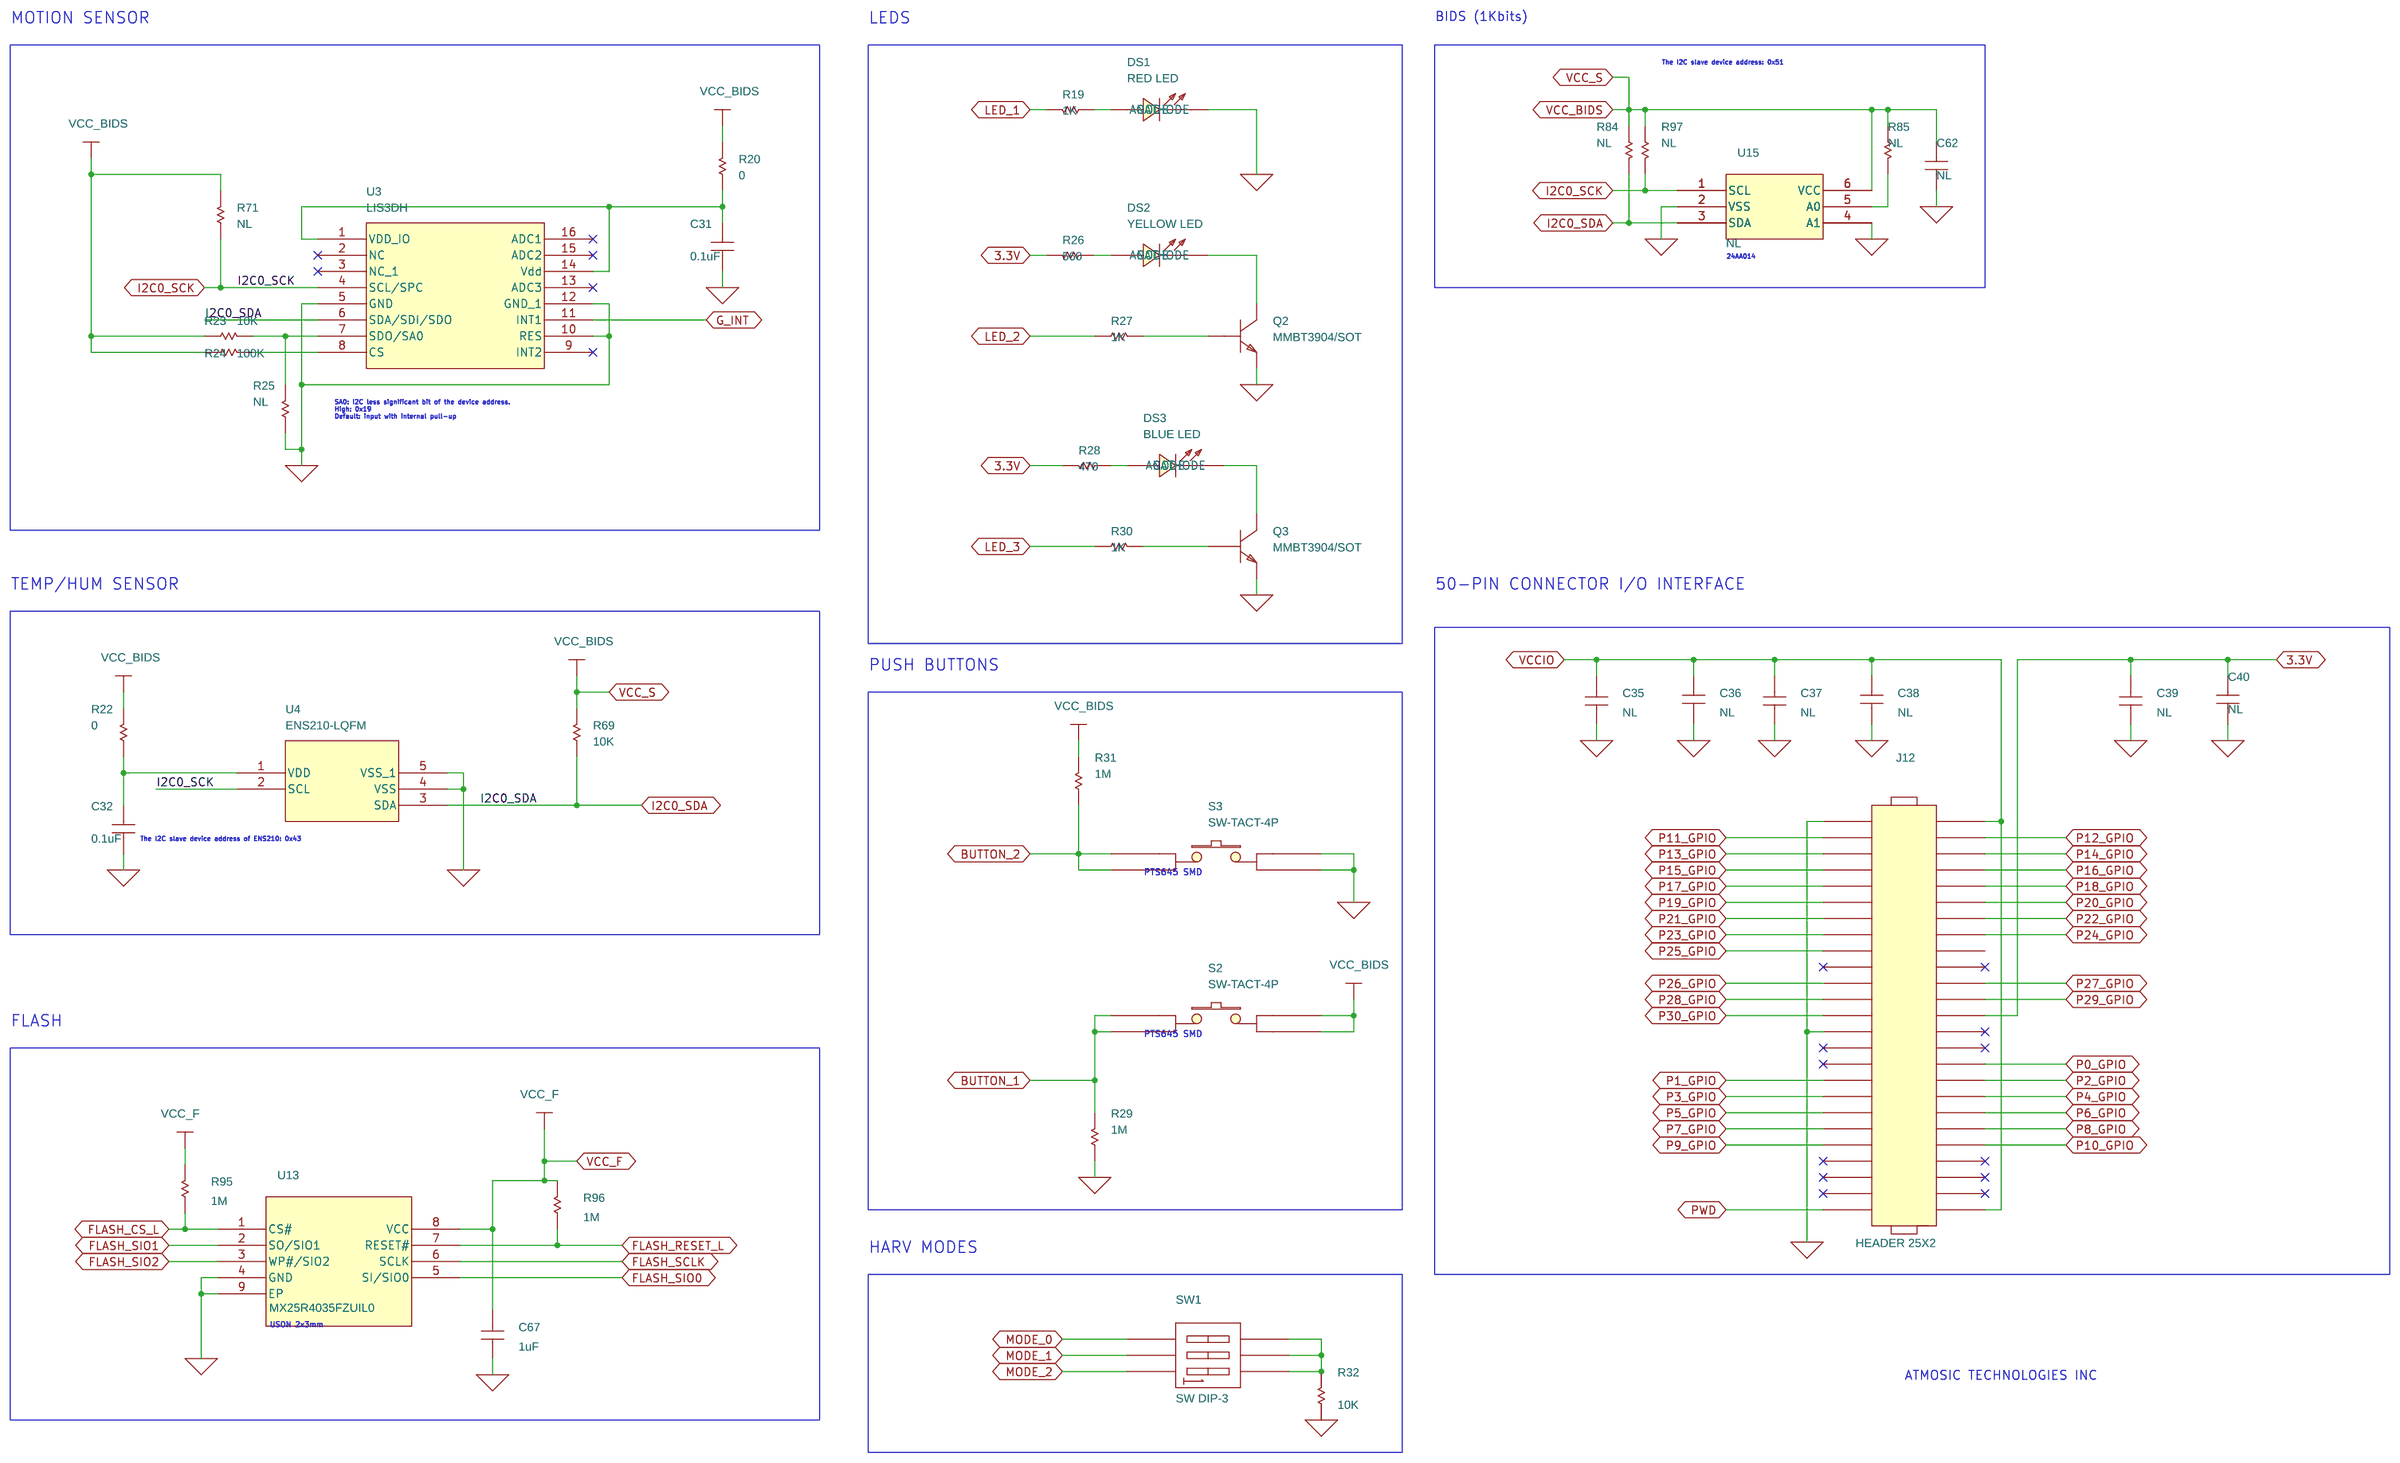
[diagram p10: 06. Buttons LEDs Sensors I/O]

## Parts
sheet 03. ATM3330E
C1  1uF  [0402]
C2  10uF  [0402]
C3  10uF  [0402]
C4  10uF  [0402]
C5  10uF  [0402]
C6  10uF  [0402]
C7  10uF  [0402]
C8  47uF  [1206]
C10  1uF  [0402]
C11  1uF  [0402]
C12  10uF  [0603]
C13  NL  [0603]
C14  10uF  [0402]
C17  1uF  [0402]
C64  1uF  [0402]
C68  NL  [0402]
J3  HEADER 3  [HDR1X3]
J26  HEADER 3  [HDR1X3]
JP1  NL  [HDR1X2]
JP5  NL  [HDR1X2]
JP26  JUMPER-2  [HDR1X2]
L1  3.3uH  [L_DFE252012F]
R6  1  [0402]
R8  1M  [0402]
R13  0  [0402]
R15  100K  [0402]
R103  0  [0402]
S1  SW-TACT-4P  [SWI-SM-PTS645]
SB2  Short  [SB]
SB6  Open  [SB]
SB9  Short  [SB]
TP1  TP-WHT  [TESTPIN]
TP3  TP-BLK  [TESTPIN]
TP4  TP-BLK  [TESTPIN]
TP5  TP-BLK  [TESTPIN]
TP23  TP-BLK  [TESTPIN]
TP25  TP-WHT  [TESTPIN]
U1  ATM3330E  [QFN-56-7X7-0.4MM-EP5.2MM]
Y1  32K XTAL  [XTAL-SMD2-2.0X1.2MM]
Y2  K301F  [XTAL-ECX-2236]
sheet 04. GPIO Mapping
C56  0.1uF  [0402]
C57  0.1uF  [0402]
C58  0.1uF  [0402]
C59  0.1uF  [0402]
C60  0.1uF  [0402]
C72  0.1uF  [0402]
JP8  JUMPER-2  [HDR1X2]
JP11  JUMPER-2  [HDR1X2]
JP25  JUMPER-2  [HDR1X2]
JP27  JUMPER-2  [HDR1X2]
R72  1M  [0402]
R74  1M  [0402]
R79  1M  [0402]
R98  1M  [0402]
R99  1M  [0402]
SB131  Short  [SB]
SB143  Short  [SB]
TP24  TP  [TESTPAD50]
U7  NX3DV2567  [XQFN16]
U9  NX3DV2567  [XQFN16]
U10  NX3DV2567  [XQFN16]
U11  NX3DV2567  [XQFN16]
U12  NX3DV2567  [XQFN16]
U16  NX3DV2567  [XQFN16]
sheet 05. RF (RFIO/WuRX/HARV)
C18  0  [0402]
C20  1.2pF  [0402]
C21  2pF  [0402]
C22  NL  [0402]
C23  10pF  [0402]
C24  NL  [0402]
C25  2.9nH  [0402]
C26  2.7pF  [0402]
C27  100pF  [0402]
C28  100pF  [0402]
C29  NL  [0402]
C30  2.7pF  [0402]
C65  10pF  [0402]
C66  NL  [0201]
J4  SMA_SL  [SMA-RA]
J5  SMA_SL  [SMA-RA]
J6  SMA_SL  [SMA-RA]
L3  NL  [0402]
L4  6.8nH  [0402]
L5  NL  [0402]
L6  10nH  [0402]
L7  12nH  [0402]
L8  15nH  [0402]
L9  10nH  [0402]
L10  12nH  [0402]
L11  4.3nH  [0402]
L12  2.4nH  [0402]
R17  0  [0402]
R18  0  [0402]
sheet 06. Buttons LEDs Sensors I/O
C31  0.1uF  [0402]
C32  0.1uF  [0402]
C35  NL  [0402]
C36  NL  [0402]
C37  NL  [0402]
C38  NL  [0402]
C39  NL  [0402]
C40  NL  [0402]
C62  NL  [0402]
C67  1uF  [0402]
DS1  RED LED  [LED-0603]
DS2  YELLOW LED  [LED-0603]
DS3  BLUE LED  [LED-0603]
J12  HEADER 25X2  [HDR25X2]
Q2  MMBT3904/SOT  [TRA-SOT23]
Q3  MMBT3904/SOT  [TRA-SOT23]
R19  1K  [0402]
R20  0  [0402]
R22  0  [0402]
R23  10K  [0402]
R24  100K  [0402]
R25  NL  [0402]
R26  560  [0402]
R27  1K  [0402]
R28  470  [0402]
R29  1M  [0402]
R30  1K  [0402]
R31  1M  [0402]
R32  10K  [0402]
R69  10K  [0402]
R71  NL  [0402]
R84  NL  [0402]
R85  NL  [0402]
R95  1M  [0402]
R96  1M  [0402]
R97  NL  [0402]
S2  SW-TACT-4P  [SWI-SM-PTS645]
S3  SW-TACT-4P  [SWI-SM-PTS645]
SW1  SW DIP-3  [SW-DIP-219-3]
U3  LIS3DH  [LGA-16-3X3]
U4  ENS210-LQFM  [SON-04-2X2MM]
U13  MX25R4035FZUIL0  [USON-8-2X3-EP]
U15  NL  [SOT23-6]
sheet 07. Harvesting
C63  0.33uF  [1206]
C76  10uF  [0402]
C77  47uF  [1206]
C78  NL  [1206]
C79  10uF  [0402]
C80  47uF  [1206]
C81  NL  [1206]
C82  NL  [1206]
C83  47uF  [1206]
D1  BAT54S  [TRA-SOT23]
D7  SS12  [SMA_CASE_403AE]
J19  OSTVN02A150  [CONN-OSTVN02A150]
J25  OSTVN02A150  [CONN-OSTVN02A150]
J29  HEADER 3  [HDR1X3]
J31  HEADER 3  [HDR1X3]
JP30  JUMPER-2  [HDR1X2]
JP31  JUMPER-2  [HDR1X2]
JP32  JUMPER-2  [HDR1X2]
L13  MPIT5020-470M-LF  [L_MPIT6028]
Q9  YJL2312A  [SOT23]
R120  0  [0402]
R122  1K  [0402]
sheet 08. MK22
C41  0.1uF  [0402]
C42  0.1uF  [0402]
C43  0.1uF  [0402]
C44  0.1uF  [0402]
C45  0.1uF  [0402]
C46  NL  [0402]
DS4  GREEN LED  [LED-0603]
J15  FCI 10118194-0001LF  [10118194-0001LF]
J27  NL  [MOLEX-105133-0031]
R38  0  [0402]
R39  0  [0402]
R40  0  [0402]
R41  0  [0402]
R42  0  [0402]
R43  0  [0402]
R45  10K  [0402]
R46  33  [0402]
R47  33  [0402]
R48  0  [0402]
R49  0  [0402]
R50  0  [0402]
R51  0  [0402]
R66  0  [0402]
R67  10k  [0402]
R83  10k  [0402]
R118  0  [0402]
R123  100K  [0402]
TC1  TC2030-IDC  [CON-TC2030-IDC]
TP6  TP  [TESTPAD50]
TP7  TP  [TESTPAD50]
TP8  TP  [TESTPAD50]
TP9  TP  [TESTPAD50]
TP10  TP  [TESTPAD50]
TP11  TP  [TESTPAD50]
TP13  TP  [TESTPAD50]
TP14  TP  [TESTPAD50]
TP15  TP  [TESTPAD50]
TP16  TP  [TESTPAD50]
U5  NSP4201MR6  [TSOP-6]
U6  MK22FN128VLH10  [LQFP-64-10X10-0.5MM]
U22  74LVC1G08GV  [SOT23-5]
sheet 09. Power
BT2  NL  [BAT-HOLDER-2032]
C47  NL  [0402]
C48  1uF  [0402]
C49  1uF  [0402]
C50  1nF  [0402]
C51  1uF  [0402]
C52  1uF  [0402]
C53  NL  [0402]
C54  1uF  [0402]
C55  1uF  [0402]
C61  0.01uF  [0402]
FD1  TEST POINT  [FID-G]
FD2  TEST POINT  [FID-G]
FD3  TEST POINT  [FID-G]
FD4  TEST POINT  [FID-G]
J21  HEADER 3  [HDR1X3]
J22  NL  [HDR1X3]
J23  HEADER 3  [HDR1X3]
J28  HEADER 3  [HDR1X3]
JP12  NL  [HDR1X2]
JP13  NL  [HDR1X2]
JP14  NL  [HDR1X2]
JP15  NL  [HDR1X2]
JP16  NL  [HDR1X2]
JP24  NL  [HDR1X2]
MT1  TEST POINT  [HOLE-250R125]
MT2  TEST POINT  [HOLE-250R125]
MT3  TEST POINT  [HOLE-250R125]
MT4  TEST POINT  [HOLE-250R125]
MT5  TEST POINT  [HOLE-250R125]
MT6  TEST POINT  [HOLE-250R125]
R53  0  [0402]
R54  NL  [0402]
R57  0  [0402]
R58  27K 1%  [0402]
R59  10K 1%  [0402]
R60  0  [0402]
R61  NL  [0402]
R62  NL  [0402]
R73  0  [0402]
R77  0  [0402]
R78  0  [0402]
R104  NL  [0402]
SB136  Short  [SB]
SB137  Short  [SB]
SB138  Short  [SB]
SB140  Short  [SB]
SB141  Short  [SB]
SB147  Short  [SB]
TP19  TP-WHT  [TESTPIN]
TP20  TP-WHT  [TESTPIN]
TP21  TP-WHT  [TESTPIN]
TP22  TP-WHT  [TESTPIN]
VR1  MIC5255-3.3YD5  [SOT23-5]
VR2  AP2127K-ADJTRG1  [SOT23-5]
VR3  AP2127K-1.8TRG1  [SOT23-5]
sheet 10. VDDIO-VCCIO Tracking
C74  1.0uF  [0402]
C75  0.1uF  [0402]
Q5  BSS84PW  [SOT-323]
R108  100K  [0402]
R109  93.1K  [0402]
R110  50  [0402]
R111  NL  [0402]
R112  0  [0402]
R113  0  [0402]
U17  MCP6001  [SC70]
U18  TMUX1237  [SC70-6]
U19  MCP6001  [SC70]
U20  MCP6001  [SC70]
U21  MCP6001  [SC70]

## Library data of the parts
C1-C8 C10-C14 C17 C18 C20-C32 C35-C68 C72 C76-C83 = SMALL_CAP
J3 J21-J23 J26 J28 J29 J31 = HEADER_3
JP1 JP5 JP8 JP11-JP16 JP24-JP27 JP30-JP32 = JUMPER-2
L1 L3-L12 = INDUCTOR
R6 R8 R13 R15 R17-R20 R22-R32 R38-R43 R45-R51 R53 R54 R57-R62 R66 R67 R69 R71-R74 R77-R79 R83-R85 R95-R99 R103 R104 R111 R118 R120 R122 = SMALL_R1
S1-S3 = SW-TACT-4P-5
SB2 SB6 SB9 SB131 SB136-SB138 SB140 SB141 SB143 SB147 = SB
TP1 TP3-TP5 TP19-TP23 TP25 = TP
U1 = ATM3332-202_1
Y1 = XTAL: Manufacture_Name: SEIKO; Manufacture_Part_Number: SC20S-7PF20PPM; Part Number: 06-0000018; Price: 0.1; Datasheet: https://www.digikey.com/short/797qhnc0
Y2 = XTAL-OSC-4P_0
TP6-TP11 TP13-TP16 TP24 = TP_0
U7 U9-U12 U16 = NX3DV2567
J4-J6 = SMA_SL
DS1-DS4 = LED
J12 = HEADER_25X2
Q2 Q3 = MMBT3904_SOT
SW1 = SW_DIP-3
U3 = LIS3DHTR_0
U4 = ENS210-LQFM_2
U13 = LM258DRG3_0
U15 = 24AA014_0
D1 = DIODE_1A2C3COM
D7 = TMP_0: Manufacture_Name: Yangzhou Yangjie Electronic; Manufacturer_Name: ON SEMI; Part Description: Schotty Rectifier Diode
J19 J25 = CON2
L13 = INDUCTOR: Manufacturer_Name: MICROGATE; Manufacturer_Part_Number: MPIT6028-680M31-LF; Part Description: 68uH
Q9 = MPF990_0: Manufacture_Name: Yangzhou Yangjie Electronic; Manufacturer_Name: YANGJIE; Part Description: MOSFET N-CH 20V 6.8MA SOT-23
J15 = USB_CONN_1_v2
J27 = USB_CONN_1
R123 = SMALL_R1: Manufacture_Name: YAGEO; Manufacture_Part_Number: RC0402JR-07100KL; Part Number: 03-2000020; Price: 0.0002; Datasheet: https://www.digikey.com/en/products/detail/yageo/RC0402JR-07100KL/726416
TC1 = TC2030-IDC
U5 = NSP4201MR6_0
U6 = MK22FN128VLH10_0
U22 = 54AS00_0
BT2 = BAT
FD1-FD4 MT1-MT6 = TEST_POINT
VR1-VR3 = VAR_REG
C74 = SMALL_CAP: Manufacture_Name: MURATA; Manufacture_Part_Number: GRT155R61E105ME01D; Part Number: 01-2000007; Price: 0.003
C75 = SMALL_CAP: Manufacture_Name: TAIYO-YUDEN; Manufacture_Part_Number: TMK105BJ104KV-F; Part Number: 01-2000003; Price: 0.0013; Vendor: TAIYO-YUDEN
Q5 = BSS84_SOT_0: Part Description: PMOS; Part Number: 06-0000057
R108 = SMALL_R1: Manufacture_Name: YAGEO; Manufacture_Part_Number: RC0402JR-07100KL; Part Number: 03-2000020; Price: 0.00053
R109 = SMALL_R1: Manufacture_Name: YAGEO; Manufacture_Part_Number: RC0402FR-0793K1L; Part Description: RES 93.1K OHM 1% 0402; Part Number: 03-2000071; Price: 0.00053
R110 = SMALL_R1: Manufacture_Name: YAGEO; Manufacture_Part_Number: RC0402JR-0750RL; Part Description: RES 50 OHM 5% 1/16W 0402; Part Number: 03-2000072; Price: 0.00053
R112 R113 = SMALL_R1: Manufacture_Name: PANASONIC; Manufacture_Part_Number: ERJ-2GE0R00X; Part Number: 03-2000018; Price: 0.00046
U17 U19-U21 = MCP6001_1: Part Number: 05-0000021
U18 = TMUX1237_0: Part Number: 05-0000022

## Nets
1.8V: J22.3 R60.2
3.0V: J21.1 J22.1 R57.2
3.3V: C39.2 C40.1 C45.1 J12.26 R26.2 R28.2 R53.2 R109.1 U6.7(USBVDD)
AVDD1: C12.1 C13.1 R6.1 U1.1(AVDD1)
AVDD1P: C4.1 JP5.1 SB9.1 U1.25(AVDD1P)
AVDDPA: J3.2 R13.1
DVDD1: C1.1 JP1.2 SB2.2 U1.30(DVDD1)
DVDD1P: C3.1 JP1.1 SB2.1 U1.27(DVDD1P)
GND_SIGNAL: BT2.2(NEG) C1.2 C2.2 C3.2 C4.2 C5.2 C6.2 C7.2 C8.1 C10.2 C11.2 C12.2 C13.2 C14.2 C17.2 C20.1 C21.1 C22.2 C24.1 C25.1 C29.1 C30.1 C31.2 C32.2 C35.1 C36.2 C37.1 C38.2 C39.1 C40.2 C41.2 C42.2 C43.2 C44.2 C45.2 C46.2 C48.1 C49.1 C51.1 C52.1 C54.1 C55.1 C56.2 C57.2 C58.2 C59.2 C60.2 C61.1 C62.2 C64.2 C66.2 C67.1 C68.2 C72.2 C74.2 C75.2 C76.2 C77.2 C78.1 C79.2 C80.1 C81.1 C82.1 C83.1 DS1.1(CATHODE) J4.2(GND1) J4.3(GND2) J5.2(GND1) J5.3(GND2) J6.2(GND1) J6.3(GND2) J12.1 J12.27 J15.5(GND) J15.S1(CASE) J15.S2(CASE) J15.S3(CASE) J15.S4(CASE) J15.S5(CASE) J15.S6(CASE) J19.2 J25.2 J27.5(GND) J27.S1(CASE) J27.S2(CASE) J27.S3(CASE) JP32.2 L5.2 L6.2 MT1.1 MT2.1 MT3.1 MT4.1 MT5.1 MT6.1 Q2.2(E) Q3.2(E) Q9.2(SOURCE) R8.1 R15.1 R25.1 R29.1 R32.1 R45.1 R59.2 R62.2 R72.1 R74.1 R79.1 R98.1 R99.1 R103.2 R108.2 R111.2 R123.2 S3.3 S3.4 SB6.2 TC1.5(GND) TP3.1(TP) TP4.1(TP) TP5.1(TP) TP23.1(TP) U1.57(EGND) U3.5(GND) U3.10(RES) U3.12(GND_1) U4.4(VSS) U4.5(VSS_1) U5.2(GND) U6.4(VSS) U6.15(VREFL) U6.16(VSSA) U6.31(VSS) U6.32(PTA18) U6.33(PTA19) U6.47(VSS) U7.6(GND) U9.6(GND) U10.6(GND) U11.6(GND) U12.6(GND) U13.4(GND) U13.9(EP) U15.2(VSS) U15.4(A1) U16.6(GND) U17.2 U18.5(S6) U19.2 U20.2 U21.2 U22.3(GND) VR1.2(GND) VR2.2(GND) VR3.2(GND) Y2.2(NC) Y2.4(NC)
VBAT: C7.1 J23.1 J26.1 J28.3 U1.20(VBAT)
VBATLI: C64.1 SB147.1 U1.28(VBATLI)
VCC_BIDS: C62.1 R20.2 R22.2 R23.1 R24.1 R31.2 R69.2 R71.2 R84.2 R85.2 R97.2 S2.3 S2.4 U10.15(1Y1) U15.6(VCC)
VCC_F: C67.2 R95.1 R96.1 U11.15(1Y1) U13.8(VCC)
VCC_USB: C49.2 C52.2 C55.2 C75.1 DS4.2(ANODE) J15.1(VBUS) J27.1(VBUS) Q5.2(S) TP21.1(TP) U5.5(VP) U17.5 U18.2(VDD) U19.5 U20.5 U21.5 VR1.1(VIN) VR1.3(EN) VR2.1(VIN) VR2.3(EN) VR3.1(VIN) VR3.3(EN)
VCCIO: C35.2 C36.1 C37.2 C38.1 C56.1 C57.1 C58.1 C59.1 C60.1 C72.1 J12.2 J12.50 J26.3 JP8.1 JP11.1 JP25.1 JP27.1 R78.2 R104.2 R113.2 U7.14(VCC) U9.14(VCC) U10.14(VCC) U11.14(VCC) U12.14(VCC) U16.14(VCC)
VCCIO_K22: C41.1 C42.1 C43.1 C44.1 JP14.1 SB138.1 TC1.1(VCC) U6.3(VDD) U6.13(VDDA) U6.14(VREFH) U6.21(VBAT) U6.26(PTA4/LLWU_P3) U6.30(VDD) U6.48(VDD) U22.5(VCC)
VDDIO: C10.1 C11.1 JP13.1 JP24.1 R112.1 SB137.1 U1.8(VDDIO) U1.39(VDDIO)
VDDIO_FLASH: JP16.1 SB141.1 U11.16(1Z)
VDDIO_SENS: JP15.1 SB140.1 U10.16(1Z)
VDDIOP: C6.1 J3.1 J23.3 JP26.2 U1.24(VDDIOP)
BBOOT: R118.1 U9.1(1Y0)
BENIGN_BOOT: R66.1 R123.1 U22.1(A)
BUTTON_1: R29.2 S2.1 S2.2 SB131.2
BUTTON_2: R31.1 S3.1 S3.2 U16.15(1Y1)
DM: R46.1 U6.6(USB0_DM)
DP: R47.1 U6.5(USB0_DP)
FLASH_CS_L: R95.2 U11.7(3Y1) U13.1(CS#)
FLASH_RESET_L: R96.2 U11.3(2Y1) U13.7(RESET#)
FLASH_SCLK: U11.11(4Y1) U13.6(SCLK)
FLASH_SIO0: U12.3(2Y1) U13.5(SI/SIO0)
FLASH_SIO1: U12.7(3Y1) U13.2(SO/SIO1)
FLASH_SIO2: U12.11(4Y1) U13.3(WP#/SIO2)
G_INT: U3.11(INT1) U10.11(4Y1)
HARV1_RFIN_N: L10.2 U1.18(RFHARV_N)
HARV1_RFIN_P: L7.2 U1.17(RFHARV_P)
I2C0_SCK: R71.1 R97.1 U3.4(SCL/SPC) U4.2(SCL) U10.7(3Y1) U15.1(SCL)
I2C0_SDA: R69.1 R84.1 U3.6(SDA/SDI/SDO) U4.3(SDA) U10.3(2Y1) U15.3(SDA)
LED_1: R19.2 U16.3(2Y1)
LED_2: R27.1 U16.7(3Y1)
LED_3: R30.1 U16.11(4Y1)
LIOn_Bat: C82.2 J25.1 J28.1 JP30.2 R122.1
MODE_0: J12.3 SW1.4(B3) U1.34(P11)
MODE_1: J12.6 SW1.5(B2) U1.37(P14)
MODE_2: J12.16 SW1.6(B1) U1.48(P24)
NO_K22: JP11.2 R74.2 R83.1 SB143.1 U7.2(S)
P0: J12.32 U1.5(P0) U9.4(2Z)
P1: J12.33 U1.6(P1) U9.8(3Z)
P2: J12.34 U1.7(P2)
P3: J12.35 U1.9(P3)
P4: J12.36 U1.10(P4)
P5: J12.37 SB131.1 U1.11(P5)
P6: J12.38 U1.12(P6) U16.16(1Z)
P7: J12.39 U1.13(P7)
P8: J12.40 J29.2 U1.14(P8)
P9: J12.41 U1.15(P9) U16.8(3Z)
P10: J12.42 U1.33(P10) U16.12(4Z)
P12: J12.4 U1.35(P12) U7.12(4Z)
P13: J12.5 U1.36(P13) U7.16(1Z)
P15: J12.7 U1.38(P15) U7.4(2Z)
P16: J12.8 U1.40(P16) U10.8(3Z)
P17: J12.9 U1.41(P17) U10.4(2Z)
P18: J12.10 U1.42(P18) U11.12(4Z)
P19: J12.11 U1.43(P19) U11.8(3Z)
P20: J12.12 U1.44(P20) U12.4(2Z)
P21: J12.13 U1.45(P21) U12.8(3Z)
P22: J12.14 U1.46(P22) U12.12(4Z)
P23: J12.15 U1.47(P23) U11.4(2Z)
P25: J12.17 R15.2 U1.49(P25) U9.16(1Z)
P26: J12.21 U1.52(P26) U10.12(4Z)
P27: J12.22 U1.53(P27) U9.12(4Z)
P28: J12.23 U1.54(P28)
P29: J12.24 U1.55(P29) U16.4(2Z)
P30: J12.25 U1.56(P30) U7.8(3Z)
PV_CELL: C14.1 J19.1 JP31.1 TP1.1(TP) U1.19(VHARV)
PWD: J12.49 R8.2 R67.1 S1.1 S1.2 U1.16(PWD)
RFIO: L11.2 U1.2(RFIO)
SWDCLK_K22: R39.1 U9.5(2Y0)
SWDIO_K22: R38.1 U9.9(3Y0)
UART0_CTS_K22: R51.1 U7.13(4Y0)
UART0_RTS_K22: R50.1 U7.1(1Y0)
UART0_RX_K22: R48.1 U7.9(3Y0)
UART0_TX_K22: R49.1 U7.5(2Y0)
UART1_CTS_K22: R43.1 TP7.1(TP)
UART1_RTS_K22: R42.1 TP6.1(TP)
UART1_RX_K22: R40.1 U22.2(B)
UART1_TX_K22: R41.1 U9.13(4Y0)
UART2_CTS_K22: TP11.1(TP) U6.44(PTC1/LLWU_P6)
UART2_RTS_K22: TP10.1(TP) U6.45(PTC2)
UART2_RX_K22: TP8.1(TP) U6.49(PTC4/LLWU_P8)
UART2_TX_K22: TP9.1(TP) U6.46(PTC3/LLWU_P7)
USB_D+: J15.3(D+) J27.3(D+) R47.2 U5.3(IO2) U5.4(IO3)
USB_D-: J15.2(D-) J27.2(D-) R46.2 U5.1(IO1) U5.6(IO4)
USE_FLASH: JP8.2 R79.2 U11.2(S) U12.2(S)
VAUX: C5.1 JP26.1 U1.26(VAUX)
VCOINCELL: BT2.1(POS) J21.3 R104.1
VSTORE: C2.1 C8.2 C68.1 C76.1 C78.2 J3.3 JP32.1 R120.2 TP25.1(TP) U1.22(VSTORE)
WURX_RFIN: C23.1 U1.3(WURX_RFIN)
XTALI_16M: U1.51(XTALO_16M) Y2.1(HOT)
XTALI_32K: SB6.1 U1.32(XTALI_32K) Y1.2
XTALO_16M: U1.50(XTALI_16M) Y2.3(HOT)
XTALO_32K: U1.31(XTALO_32K) Y1.1
N16735640: JP5.2 R6.2 SB9.2
N16873328: L1.1 U1.21(LEXT1)
N16873338: L1.2 U1.23(LEXT2)
N16893506: C17.1 R13.2 U1.4(AVDDPA)
N17095028: C47.2 C48.2 R53.1 R54.1 VR1.5(VOUT)
N17095050: C47.1 C61.2 R54.2 VR1.4(ADJ)
N17095106: J21.2 JP12.2 R73.1 SB136.2
N17095108: J23.2 JP13.2 JP15.2 JP16.2 R77.2 SB137.2 SB140.2 SB141.2
N17095279: C53.2 C54.2 R60.1 R61.1 VR3.5(VOUT)
N17095319: C53.1 R61.2 R62.1 VR3.4(ADJ)
N17095349: J28.2 JP12.1 SB136.1 SB147.2
N17095531: C50.2 C51.2 R57.1 R58.1 VR2.5(VOUT)
N17095557: C50.1 R58.2 R59.1 VR2.4(ADJ)
N17096185: J22.2 JP14.2 JP24.2 R78.1 SB138.2 TP20.1(TP)
N17098002: R103.1 U1.29(RES)
N17100046: R99.2 SB143.2 TP24.1(TP) U9.2(S)
N17100334: JP25.2 R72.2 U10.2(S)
N17101171: C18.2 J4.1(IO)
N17101173: C18.1 C65.2 C66.1 L3.1
N17101183: C20.2 C65.1 L12.1
N17101189: C21.2 L11.1 L12.2
N17101247: C22.1 L3.2
N17101303: J5.1(IO) R17.2
N17101305: C24.2 L4.1 R17.1
N17101311: C23.2 C25.2 L4.2
N17101384: C26.2 C29.2 L5.1 L9.1 R18.2
N17101386: C26.1 C27.2 L6.1
N17101427: C27.1 L7.1 L8.2
N17101464: J6.1(IO) R18.1
N17101492: C28.1 L8.1 L10.1
N17101511: C28.2 C30.2 L9.2
N17102737: DS1.2(ANODE) R19.1
N17102803: C31.1 R20.1 U3.1(VDD_IO) U3.14(Vdd)
N17102805: C32.1 R22.1 U4.1(VDD)
N17102917: DS2.2(ANODE) R26.1
N17102919: DS2.1(CATHODE) Q2.3(C)
N17103005: R23.2 R25.2 U3.7(SDO/SA0)
N17103017: Q2.1(B) R27.2
N17103021: R24.2 U3.8(CS)
N17103073: DS3.2(ANODE) R28.1
N17103075: DS3.1(CATHODE) Q3.3(C)
N17103123: Q3.1(B) R30.2
N17103301: R32.2 SW1.1(A1) SW1.2(A2) SW1.3(A3)
N17103574: R85.1 U15.5(A0)
N17105483: R67.2 U6.2(PTE1/LLWU_P0)
N17105496: R83.2 TP15.1(TP) U6.58(PTD1)
N17105530: R38.2 U6.63(PTD6/LLWU_P15)
N17105555: R39.2 U6.62(PTD5)
N17105589: R66.2 U6.61(PTD4/LLWU_P14)
N17105614: R40.2 U6.60(PTD3)
N17105656: R41.2 U6.59(PTD2/LLWU_P13)
N17105670: R42.2 U6.54(PTC9)
N17105708: R43.2 U6.53(PTC8)
N17105834: DS4.1(CATHODE) R45.2
N17106014: R48.2 U6.40(PTB17)
N17106031: R49.2 U6.39(PTB16)
N17106052: R50.2 U6.38(PTB3)
N17106071: R51.2 U6.37(PTB2)
N17106085: C46.1 TC1.3(NRESET) U6.34(RESET_B)
N17106116: TC1.4(SWCLK) U6.22(PTA0)
N17106118: TC1.6(SWO) U6.24(PTA2)
N17106120: TC1.2(SWDIO) U6.25(PTA3)
N17109714: J26.2 S1.3 S1.4
N17114657: JP27.2 R98.2 U16.2(S)
N17182443: R108.1 R109.2 U17.3
N17182456: U18.1(S2) U19.3 U20.1 U20.4
N17182464: U18.6(SEL) U19.1
N17182470: U17.1 U17.4 U18.3(S1) U19.4
N17182563: Q5.3(D) R111.1 R113.1 U21.3
N17182569: R112.2 U20.3
N17182581: Q5.1(G) U21.1
N17182601: R110.2 U18.4(D)
N17182603: C74.1 R110.1 U21.4
N17186282: R118.2 U22.4(Y)
N17192183: D1.1(A) R120.1
N17192187: D1.2(K) J31.1
N17192259: C63.2 D1.3(C)
N17192292: J31.2 JP30.1 R122.2
N17192308: C63.1 J29.1
N17192370: C77.1 C83.2 D7.2 J31.3
N17192375: C79.1 C80.2 C81.2 JP31.2 L13.1
N17192465: D7.1 L13.2 Q9.3(DRAIN)
N17192502: J29.3 Q9.1(GATE)
N17215839: R77.1 TP19.1(TP)
N17215840: R73.2 TP22.1(TP)
N17216043: TP16.1(TP) U6.64(PTD7)
N17216044: TP13.1(TP) U6.56(PTC11/LLWU_P11)
N17216045: TP14.1(TP) U6.57(PTC0/LLWU_P12)

Not connected (* = marked no-connect by the designer): FD1 1*; FD2 1*; FD3 1*; FD4 1*; J12 18 19* 20* 28* 29* 30* 31* 43* 44* 45* 46* 47* 48*; J15 4(IO)*; J27 4(IO)*; U3 2(NC)* 3(NC_1)* 9(INT2)* 13(ADC3)* 15(ADC2)* 16(ADC1)*; U6 1(PTE0/CLKOUT32K)* 8(NC)* 9(ADC0_DP0/ADC1_DP3)* 10(ADC0_DM0/ADC1_DM3)* 11(ADC1_DP0/ADC0_DP3)* 12(ADC1_DM0/ADC0_DM3)* 17(VREF_OUT)* 18(DAC0_OUT)* 19(XTAL32)* 20(EXTAL32)* 23(PTA1)* 27(PTA5)* 28(PTA12)* 29(PTA13/LLWU_P4)* 35(PTB0/LLWU_P5)* 36(PTB1)* 41(PTB18)* 42(PTB19)* 43(PTC0)* 50(PTC5/LLWU_P9)* 51(PTC6/LLWU_P10)* 52(PTC7)* 55(PTC10)*; U7 3(2Y1)* 7(3Y1)* 10(N_C_)* 11(4Y1)* 15(1Y1)*; U9 3(2Y1)* 7(3Y1)* 10(N_C_)* 11(4Y1)* 15(1Y1)*; U10 1(1Y0)* 5(2Y0)* 9(3Y0)* 10(N_C_)* 13(4Y0)*; U11 1(1Y0)* 5(2Y0)* 9(3Y0)* 10(N_C_)* 13(4Y0)*; U12 1(1Y0)* 5(2Y0)* 9(3Y0)* 10(N_C_)* 13(4Y0)* 15(1Y1)* 16(1Z)*; U16 1(1Y0)* 5(2Y0)* 9(3Y0)* 10(N_C_)* 13(4Y0)*

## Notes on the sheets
sheet 1
- ATM3330e EVALUATION BOARD (with J-Link OB)
- Release Date
- Revision
- Design Eng.
- Design Notes
- 10/03/21
- -00
- AD
- Initial release
- 12/01/21
- -10
- AD
- Ground pin 33 of MK22
  Change Paris Part Number to ATM3330e
  Change resistors and supplies to adjust brightness of LEDs
  Change R61 to 20K and R62 to 16K due to availability
  Change several components to NL by default
  Short SB119 by default
  Add two SB121 and SB122 to VDDPA
- 5/25/22
- -20
- AD
- Remove the 20-pin Interface connector J8
  Remove the Arduino connectors J10, J11, J13, J14
  Remove the Trace/Debug connectors J7, J9
  All GPIOS directly connected to J12
  Analog switches are used to connect/disconnect K22 and peripherals
- Loaded R69 I2C data pull-up
  915MHz Harvester Match
  Updated RFIO Match
  Updated Li-Ion charge pump ckt
  Changed VAUX cap to 4.7uF and C63 to 0ohm
  Load C17 (VDDPA bypass) with 1uF
- 7/20/22
- -21
- AD
- 11/08/22
- -22
- AD
- Updated U1 pin names for pins 20 (VBAT) and 28 (VBATLI)
  Renamed nets: VBATT to VBAT, and VBATTLI to VBATLI
  Updated RFIO Match (L11, C21, L12, C20)
  Updated WuRx Match (C25, L4, C24)
- 11/21/22
- -31
- AD
- Changed JP29 to J28 to select between VBAT and VBATLI
  Removed C9 and JP3 (harvesting meter), added a TP25 (VSTORE)
  Added R99 to keep SWD and BBOOT connected by default
  Added short SB145 and R101, R102 to Li-Ion Charging Ckt
  Added short SB146 to ground the negative terminal of PV cell
  Changed C63 (0ohms on RES pin 29 of U1) to R103 (0ohms)
  Added R104 as an option to connect VCCIO to Coin Cell
  Added Brownout/LPComp Ckt (R105, R106, C73)
  Added R100 between P13 and U7
  Changed 32kHz clock for boost ckt from P13 to P4
- 03/31/23
- -32
- AD
- Modified the description for C12
- Added VCCIO tracking circuit. Changed Sensor control from I2C1 (P6/P7) to I2C0 (P16/P17).
  Added inductive boost circuit option.
- 08/15/23
- -40
- AD
- 12/21/23
- -50
- AD
- Add R123 100Kohm (0402) resistor to pull down the BENIGN_BOOT signal.
- 9/18/24
- -51
- JoeC
- Add Notes for "Li-Ion Charging Ckts".
- 10/29/25
- -52
- AD
- Changed C5 (VAUX) and C6 (VDDIOP) to 10uF
- ATMOSIC TECHNOLOGIES INC
- Atmosic Technologies, Inc
- 2105 South Bascom Avenue, Suite 220
  Campbell, CA 95008
- Atmosic Technologies Proprietary and Confidential
sheet 2
- Page 1 - Revision notes
  Page 2 - Block diagram
  Page 3 - ATM3430E, decoupling, Li-Ion charging ckt
  Page 4 - GPIO Mapping, Analog switches
  Page 5 - RF matching circuits
  Page 6 - Sensors, Flash, LEDs, Buttons, I/O Interface Connector
  Page 7 - Harvesting and Booster Ckt
  Page 8 - MK22 Controller
  Page 9 - Power supplies and configurations
  Page 10 - VDDIO-VCCIO tracking circuit
  Page 11 - Jumper settings for common Operation Modes
- Block Diagram
- PV Cell
  Conn
- Li-Ion Bat
  Conn
- Ext Supply
  Conn
- USB
  Conn
- On-board Power Supplies
- LEDs
- Buttons
- Sensors
- RF Harvester
  Match
- SMA Conn
- Programming
  Pads
- MK22
- 50-pin
  Connector
- Analog
  Switches
- ATM3330E
- Wake-up Rx
  Match
- SMA Conn
- Flash
- GPIOs: P0 - P30
- BLE Tx/Rx
  Match
- SMA Conn
- Reset Button
- ATMOSIC TECHNOLOGIES INC
sheet 3
- Change C12 to 22uF if needs
  to operate below -10°C
- 16MHz XTAL
- Power down switch
- PTS645 SMD
- Benign boot
- 7X7 QFN
- ATMOSIC TECHNOLOGIES INC
- Atmosic Technologies Proprietary and Confidential
sheet 4
- GPIO MUX
- CONNECT SENSORS TO ATM3330
- ISOLATE MK22 FROM ATM3330
- CONNECT FLASH TO ATM3330
- Install to
  connect Sensors
- Install to
  isolate MK22
- Install to
  connect Flash
- CONNECT LEDS/BUTTONS TO ATM3330
- Assert to
  isolate MK22
- Install to
  connect LEDs
  and Buttons
- ATMOSIC TECHNOLOGIES INC
- Atmosic Technologies Proprietary and Confidential
sheet 5
- Reserved for Internal Use Only
- R122 is used for
  measurement only
- J25 - PCB Block Terminal Connector
  Li-Ion Battery wires connect to the PCB here
- PV Cell connector
- J19 - PCB Block Terminal Connector
  PV cell wires connect to the PCB here
- Li-Ion Charging Ckts
- ATMOSIC TECHNOLOGIES INC
sheet 6
- USB ESD
- (Benign Boot
       /
     UART1_RX)
- Pull-down resistor added because the signal
  could not be forced LOW when MK22 is not active
- 90 OHM DIFF PAIR
- USB
- USB OPTION
- MOLEX-105133-031
- J-Link OB
  Programming Pads
- ATMOSIC TECHNOLOGIES INC
sheet 7
- VCC_USB
- Supply for MK22 USB
- VBAT/LI
- VDDIO
- On-Board Voltage Regulators
- For current
  measurements
- Supply for VCCIO
- BAT 2032
- Supply for VBAT
  and/or VCCIO
- For current
  measurements
- Jumper on pins 1-2 for
  external Li-Ion through VBATLI
  Jumper on pins 2-3 to connect
  VBAT to VBATLI for VBAT operation
- VCCIO
- MOUNTING HOLES
- BOARD FIDUCIALS
- ATMOSIC TECHNOLOGIES INC
sheet 8
- VDDIO < 1.72V: VCCIO = 1.71V
  VDDIO >=1.72V: VCCIO = VDDIO
- Remove R112 when
  using Interface Board
- Remove R113 when
  using Interface Board
sheet 9
- Common EVB Operation Modes
- ATMOSIC TECHNOLOGIES INC
sheet 10
- BLE front-end match
- RFIO
- ohm
- ESD150-B1-W0201
- Note:
  For inductors, use MHQ series from TDK.
  For capacitors, use Johanson
- WuRx match
- RFIN
- Note:
  For C25 and L4, use  LQW15AN2N9G80D and LQW15AN6N8G80D from Murata
- RF Harvester front-end & ANT
- Note: This match is for 915MHz
  Use Murata Wirewound inductors.
  For capacitors, use Johanson.
- RFIN_HARV
- ATMOSIC TECHNOLOGIES INC
- Atmosic Technologies Proprietary and Confidential
sheet 11
- MOTION SENSOR
- LEDS
- BIDS (1Kbits)
- The I2C slave device address: 0x51
- 24AA014
- SA0: I2C less significant bit of the device address.
  High: 0x19
  Default: input with internal pull-up
- TEMP/HUM SENSOR
- 50-PIN CONNECTOR I/O INTERFACE
- PUSH BUTTONS
- The I2C slave device address of ENS210: 0x43
- PTS645 SMD
- FLASH
- PTS645 SMD
- HARV MODES
- USON 2x3mm
- ATMOSIC TECHNOLOGIES INC
